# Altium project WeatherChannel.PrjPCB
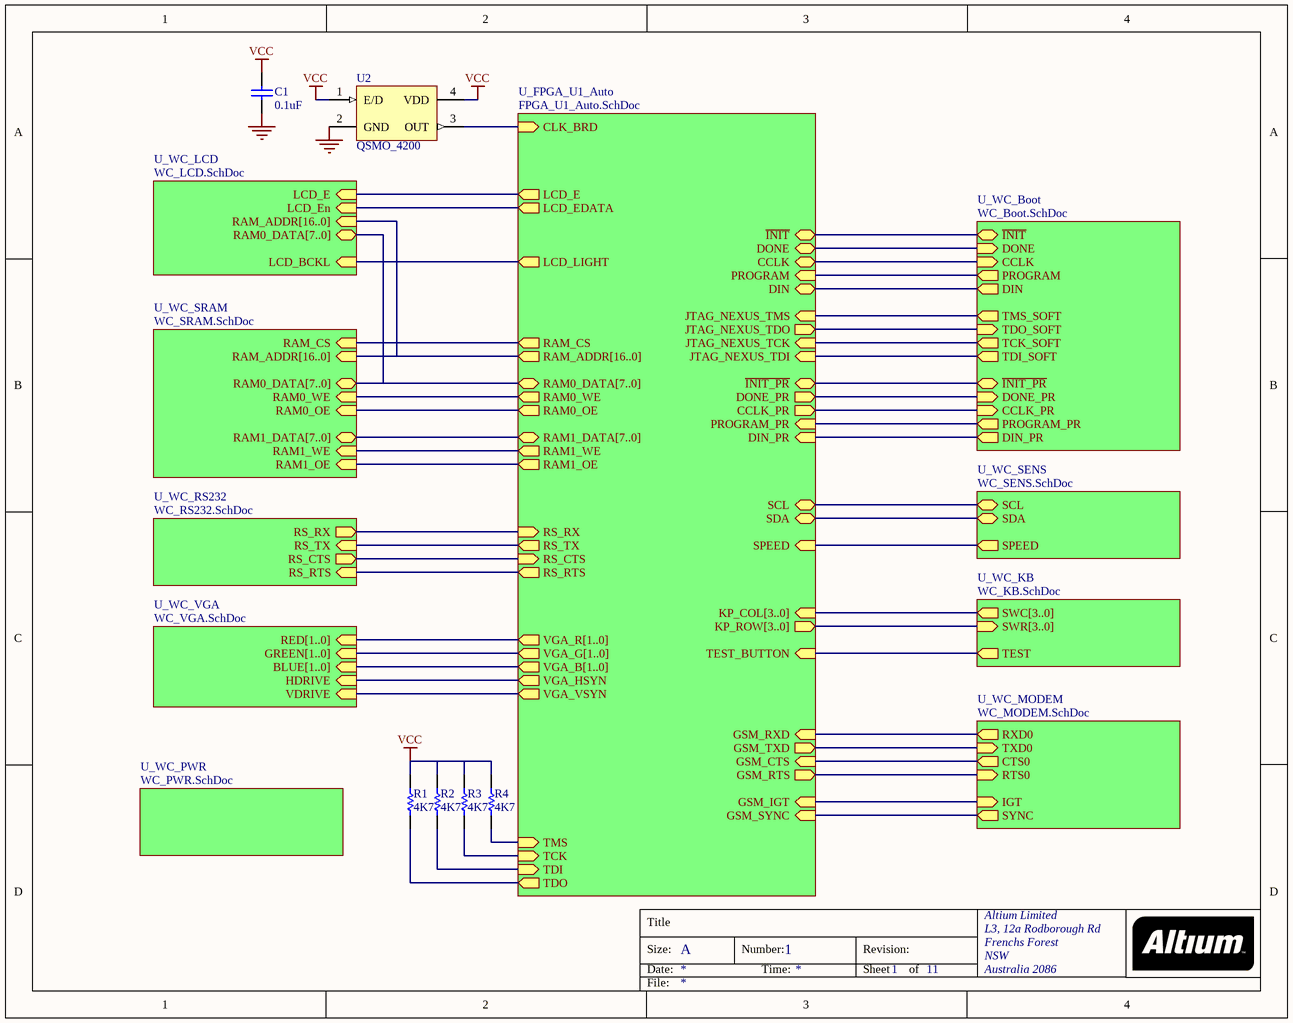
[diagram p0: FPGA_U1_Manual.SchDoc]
11 sheets, 128 parts. Net scope: hierarchical (ports join the sheet entries above them; power ports are global).
Board file: WeatherChannel.PcbDoc
Sheets:
  FPGA_U1_Manual.SchDoc
    U_FPGA_U1_Auto = FPGA_U1_Auto.SchDoc
    U_WC_SENS = WC_SENS.SchDoc
    U_WC_LCD = WC_LCD.SchDoc
    U_WC_SRAM = WC_SRAM.SchDoc
    U_WC_VGA = WC_VGA.SchDoc
    U_WC_RS232 = WC_RS232.SchDoc
    U_WC_KB = WC_KB.SchDoc
    U_WC_PWR = WC_PWR.SchDoc
    U_WC_Boot = WC_Boot.SchDoc
    U_WC_MODEM = WC_MODEM.SchDoc

## Sheet FPGA_U1_Manual.SchDoc
size A; Organization: Altium Limited; Address1: L3, 12a Rodborough Rd; Address2: Frenchs Forest; Address3: NSW; Address4: Australia 2086; DocumentNumber: 1; SheetNumber: 1; SheetTotal: 11

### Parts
C1  0.1uF  [CC2012-0805]
R1  4K7  [CC2012-0805]
R2  4K7  [CC2012-0805]
R3  4K7  [CC2012-0805]
R4  4K7  [CC2012-0805]
U2  QSMO_4200  [QSMO_4200]

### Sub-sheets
U_FPGA_U1_Auto = FPGA_U1_Auto.SchDoc: CLK_BRD (in), SPEED (in), JTAG_NEXUS_TCK (in), JTAG_NEXUS_TDI (in), JTAG_NEXUS_TDO (out), JTAG_NEXUS_TMS (in), KP_COL[3..0] (in), KP_ROW[3..0] (out), LCD_E (out), LCD_EDATA (out), LCD_LIGHT (out), RAM_ADDR[16..0] (out), RAM_CS (out), RAM0_DATA[7..0] (bidir), RAM0_OE (out), RAM0_WE (out), RAM1_DATA[7..0] (bidir), RAM1_OE (out), RAM1_WE (out), RS_CTS (in), RS_RTS (out), RS_RX (in), RS_TX (out), SCL (bidir), SDA (bidir), TEST_BUTTON (in), VGA_B[1..0] (out), VGA_G[1..0] (out), VGA_HSYN (out), VGA_R[1..0] (out), VGA_VSYN (out), CCLK (bidir), DONE (bidir), PROGRAM (in), TCK (in), TDI (in), TDO (out), TMS (in), GSM_CTS (in), GSM_IGT (in), GSM_RTS (out), GSM_RXD (in), GSM_SYNC (in), GSM_TXD (out), CCLK_PR (out), DIN_PR (in), DONE_PR (out), PROGRAM_PR (in), ~{INIT_PR} (bidir), ~{INIT} (bidir), DIN (bidir)
U_WC_Boot = WC_Boot.SchDoc: ~{INIT} (bidir), DONE (in), CCLK (in), ~{INIT_PR} (bidir), DONE_PR (in), CCLK_PR (in), DIN (out), DIN_PR (out), PROGRAM (out), PROGRAM_PR (out), TMS_SOFT (out), TDO_SOFT (in), TCK_SOFT (out), TDI_SOFT (out)
U_WC_KB = WC_KB.SchDoc: TEST (out), SWR[3..0] (in), SWC[3..0] (out)
U_WC_LCD = WC_LCD.SchDoc: LCD_E (in), LCD_BCKL (in), LCD_En (in), RAM0_DATA[7..0] (bidir), RAM_ADDR[16..0] (in)
U_WC_MODEM = WC_MODEM.SchDoc: TXD0 (in), RXD0 (out), IGT (in), RTS0 (in), CTS0 (out), SYNC (out)
U_WC_PWR = WC_PWR.SchDoc: no entries
U_WC_RS232 = WC_RS232.SchDoc: RS_RTS (in), RS_TX (in), RS_CTS (out), RS_RX (out)
U_WC_SENS = WC_SENS.SchDoc: SCL (bidir), SDA (bidir), SPEED (out)
U_WC_SRAM = WC_SRAM.SchDoc: RAM0_WE (in), RAM0_OE (in), RAM1_WE (in), RAM1_OE (in), RAM_CS (in), RAM0_DATA[7..0] (bidir), RAM1_DATA[7..0] (bidir), RAM_ADDR[16..0] (in)
U_WC_VGA = WC_VGA.SchDoc: RED[1..0] (in), GREEN[1..0] (in), BLUE[1..0] (in), HDRIVE (in), VDRIVE (in)

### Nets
GND: C1.2 U2.2(GND)
VCC: C1.1 R1.1 R2.1 R3.1 R4.1 U2.1(E/D) U2.4(VDD)
CCLK: sheet U_FPGA_U1_Auto/CCLK, sheet U_WC_Boot/CCLK
CCLK_PR: sheet U_FPGA_U1_Auto/CCLK_PR, sheet U_WC_Boot/CCLK_PR
CLK_BRD: U2.3(OUT) ; sheet U_FPGA_U1_Auto/CLK_BRD
DIN: sheet U_FPGA_U1_Auto/DIN, sheet U_WC_Boot/DIN
DIN_PR: sheet U_FPGA_U1_Auto/DIN_PR, sheet U_WC_Boot/DIN_PR
DONE: sheet U_FPGA_U1_Auto/DONE, sheet U_WC_Boot/DONE
DONE_PR: sheet U_FPGA_U1_Auto/DONE_PR, sheet U_WC_Boot/DONE_PR
GSM_CTS: sheet U_FPGA_U1_Auto/GSM_CTS, sheet U_WC_MODEM/CTS0
GSM_IGT: sheet U_FPGA_U1_Auto/GSM_IGT, sheet U_WC_MODEM/IGT
GSM_RTS: sheet U_FPGA_U1_Auto/GSM_RTS, sheet U_WC_MODEM/RTS0
GSM_RXD: sheet U_FPGA_U1_Auto/GSM_RXD, sheet U_WC_MODEM/RXD0
GSM_SYNC: sheet U_FPGA_U1_Auto/GSM_SYNC, sheet U_WC_MODEM/SYNC
GSM_TXD: sheet U_FPGA_U1_Auto/GSM_TXD, sheet U_WC_MODEM/TXD0
~{INIT}: sheet U_FPGA_U1_Auto/~{INIT}, sheet U_WC_Boot/~{INIT}
~{INIT_PR}: sheet U_FPGA_U1_Auto/~{INIT_PR}, sheet U_WC_Boot/~{INIT_PR}
JTAG_NEXUS_TCK: sheet U_FPGA_U1_Auto/JTAG_NEXUS_TCK, sheet U_WC_Boot/TCK_SOFT
JTAG_NEXUS_TDI: sheet U_FPGA_U1_Auto/JTAG_NEXUS_TDI, sheet U_WC_Boot/TDI_SOFT
JTAG_NEXUS_TDO: sheet U_FPGA_U1_Auto/JTAG_NEXUS_TDO, sheet U_WC_Boot/TDO_SOFT
JTAG_NEXUS_TMS: sheet U_FPGA_U1_Auto/JTAG_NEXUS_TMS, sheet U_WC_Boot/TMS_SOFT
LCD_BCKL: sheet U_FPGA_U1_Auto/LCD_LIGHT, sheet U_WC_LCD/LCD_BCKL
LCD_E: sheet U_FPGA_U1_Auto/LCD_E, sheet U_WC_LCD/LCD_E
LCD_EDATA: sheet U_FPGA_U1_Auto/LCD_EDATA, sheet U_WC_LCD/LCD_En
PROGRAM: sheet U_FPGA_U1_Auto/PROGRAM, sheet U_WC_Boot/PROGRAM
PROGRAM_PR: sheet U_FPGA_U1_Auto/PROGRAM_PR, sheet U_WC_Boot/PROGRAM_PR
RAM0_OE: sheet U_FPGA_U1_Auto/RAM0_OE, sheet U_WC_SRAM/RAM0_OE
RAM0_WE: sheet U_FPGA_U1_Auto/RAM0_WE, sheet U_WC_SRAM/RAM0_WE
RAM1_OE: sheet U_FPGA_U1_Auto/RAM1_OE, sheet U_WC_SRAM/RAM1_OE
RAM1_WE: sheet U_FPGA_U1_Auto/RAM1_WE, sheet U_WC_SRAM/RAM1_WE
RAM_CS: sheet U_FPGA_U1_Auto/RAM_CS, sheet U_WC_SRAM/RAM_CS
RS_CTS: sheet U_FPGA_U1_Auto/RS_CTS, sheet U_WC_RS232/RS_CTS
RS_RTS: sheet U_FPGA_U1_Auto/RS_RTS, sheet U_WC_RS232/RS_RTS
RS_RX: sheet U_FPGA_U1_Auto/RS_RX, sheet U_WC_RS232/RS_RX
RS_TX: sheet U_FPGA_U1_Auto/RS_TX, sheet U_WC_RS232/RS_TX
SCL: sheet U_FPGA_U1_Auto/SCL, sheet U_WC_SENS/SCL
SDA: sheet U_FPGA_U1_Auto/SDA, sheet U_WC_SENS/SDA
SPEED: sheet U_FPGA_U1_Auto/SPEED, sheet U_WC_SENS/SPEED
TCK: R3.2 ; sheet U_FPGA_U1_Auto/TCK
TDI: R2.2 ; sheet U_FPGA_U1_Auto/TDI
TDO: R1.2 ; sheet U_FPGA_U1_Auto/TDO
TEST: sheet U_FPGA_U1_Auto/TEST_BUTTON, sheet U_WC_KB/TEST
TMS: R4.2 ; sheet U_FPGA_U1_Auto/TMS
VGA_HSYN: sheet U_FPGA_U1_Auto/VGA_HSYN, sheet U_WC_VGA/HDRIVE
VGA_VSYN: sheet U_FPGA_U1_Auto/VGA_VSYN, sheet U_WC_VGA/VDRIVE

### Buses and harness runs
bus sheet U_FPGA_U1_Auto/KP_COL[3..0] = sheet U_WC_KB/SWC[3..0]
bus sheet U_FPGA_U1_Auto/KP_ROW[3..0] = sheet U_WC_KB/SWR[3..0]
bus sheet U_FPGA_U1_Auto/RAM0_DATA[7..0] = sheet U_WC_LCD/RAM0_DATA[7..0] = sheet U_WC_SRAM/RAM0_DATA[7..0]
bus sheet U_FPGA_U1_Auto/RAM1_DATA[7..0] = sheet U_WC_SRAM/RAM1_DATA[7..0]
bus sheet U_FPGA_U1_Auto/RAM_ADDR[16..0] = sheet U_WC_LCD/RAM_ADDR[16..0] = sheet U_WC_SRAM/RAM_ADDR[16..0]
bus sheet U_FPGA_U1_Auto/VGA_B[1..0] = sheet U_WC_VGA/BLUE[1..0]
bus sheet U_FPGA_U1_Auto/VGA_G[1..0] = sheet U_WC_VGA/GREEN[1..0]
bus sheet U_FPGA_U1_Auto/VGA_R[1..0] = sheet U_WC_VGA/RED[1..0]

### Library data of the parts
C1 = CAP: Capacitor
R1-R4 = RES: Resistor
U2 = QSMO_4200: Surface Mount Crystal Oscillator

## Sheet FPGA_U1_Auto.SchDoc
size A2; Generated From FPGA Project: WeatherChannel.PrjFpg; UNUSED_SPECIAL: RouteSeparate; UNUSED_IO: NoERC; VREF: NoERC; UNUSED_INPUT: NoERC; DocumentNumber: 11; SheetNumber: 11; SheetTotal: 11
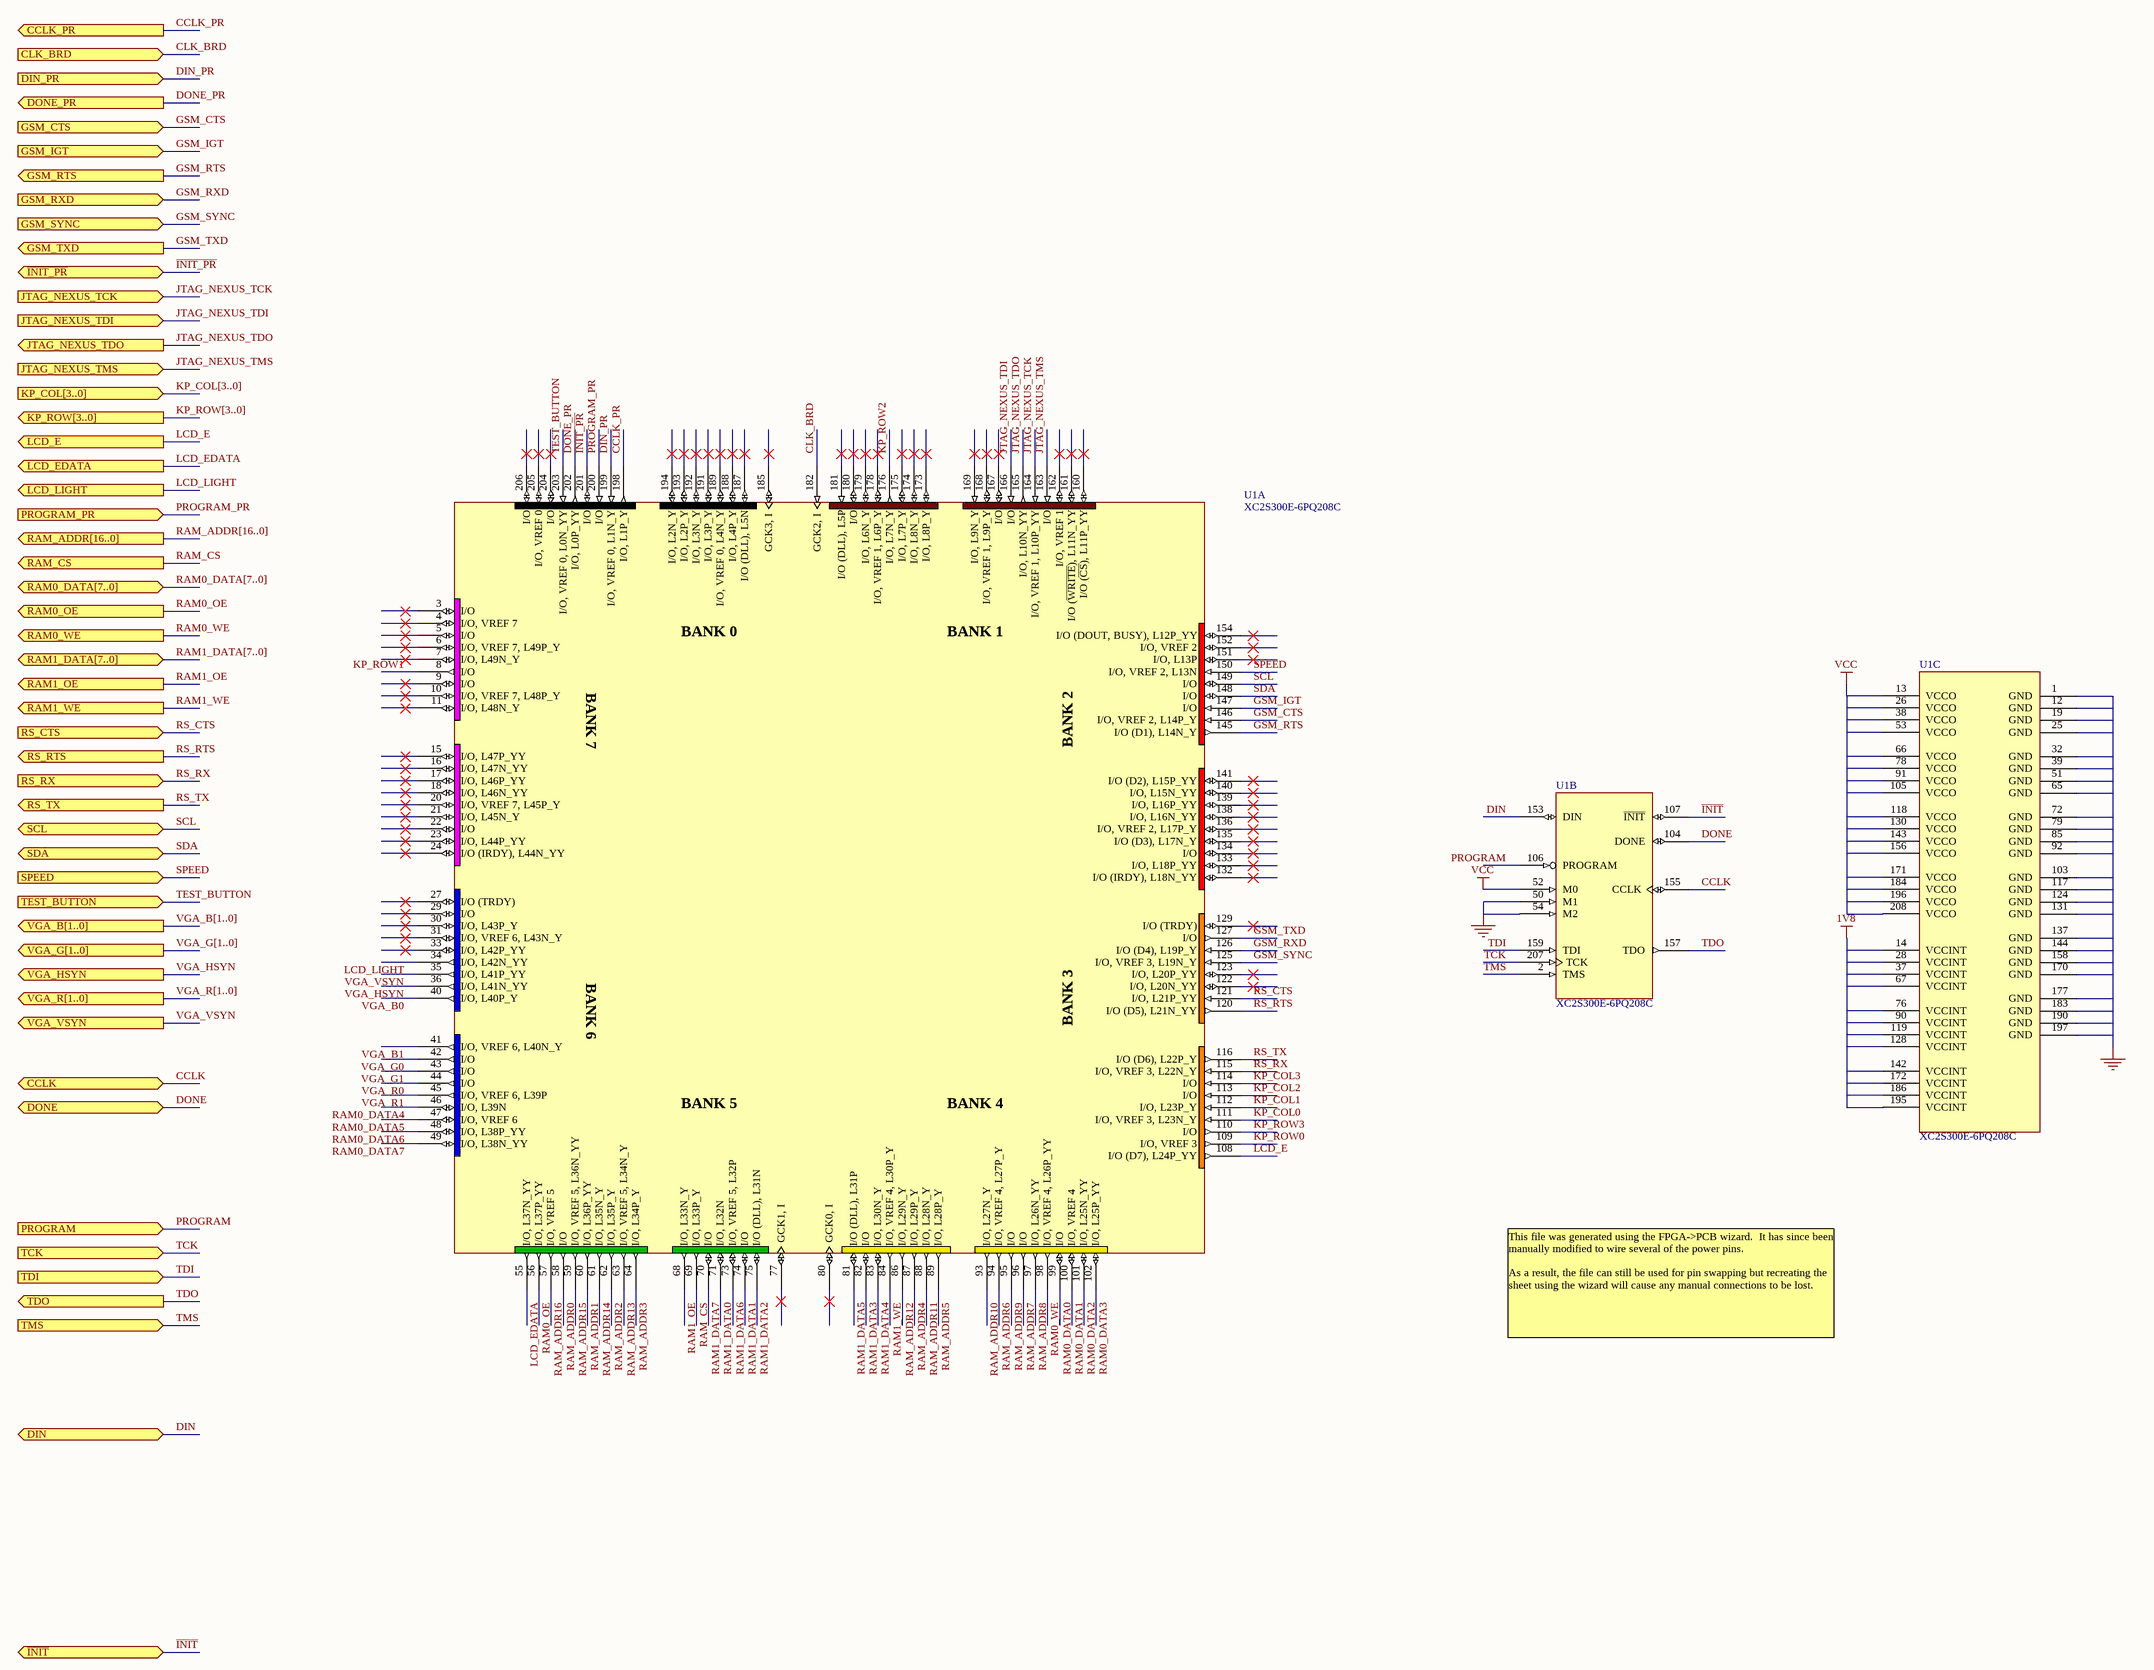
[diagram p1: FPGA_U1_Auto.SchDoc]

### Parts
U1  XC2S300E-6PQ208C  [PQ208]  (parts A,B,C of 3)

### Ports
CCLK (bidir), CCLK_PR (out), CLK_BRD (in), DIN (bidir), DIN_PR (in), DONE (bidir), DONE_PR (out), GSM_CTS (in), GSM_IGT (in), GSM_RTS (out), GSM_RXD (in), GSM_SYNC (in), GSM_TXD (out), JTAG_NEXUS_TCK (in), JTAG_NEXUS_TDI (in), JTAG_NEXUS_TDO (out), JTAG_NEXUS_TMS (in), KP_COL[3..0] (in), KP_ROW[3..0] (out), LCD_E (out), LCD_EDATA (out), LCD_LIGHT (out), PROGRAM (in), PROGRAM_PR (in), RAM0_DATA[7..0] (bidir), RAM0_OE (out), RAM0_WE (out), RAM1_DATA[7..0] (bidir), RAM1_OE (out), RAM1_WE (out), RAM_ADDR[16..0] (out), RAM_CS (out), RS_CTS (in), RS_RTS (out), RS_RX (in), RS_TX (out), SCL (bidir), SDA (bidir), SPEED (in), TCK (in), TDI (in), TDO (out), TEST_BUTTON (in), TMS (in), VGA_B[1..0] (out), VGA_G[1..0] (out), VGA_HSYN (out), VGA_R[1..0] (out), VGA_VSYN (out), ~{INIT_PR} (bidir), ~{INIT} (bidir)

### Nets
1V8: U1.14(VCCINT) U1.28(VCCINT) U1.37(VCCINT) U1.67(VCCINT) U1.76(VCCINT) U1.90(VCCINT) U1.119(VCCINT) U1.128(VCCINT) U1.142(VCCINT) U1.172(VCCINT) U1.186(VCCINT) U1.195(VCCINT)
GND: U1.1(GND) U1.12(GND) U1.19(GND) U1.25(GND) U1.32(GND) U1.39(GND) U1.50(M1) U1.51(GND) U1.54(M2) U1.65(GND) U1.72(GND) U1.79(GND) U1.85(GND) U1.92(GND) U1.103(GND) U1.117(GND) U1.124(GND) U1.131(GND) U1.137(GND) U1.144(GND) U1.158(GND) U1.170(GND) U1.177(GND) U1.183(GND) U1.190(GND) U1.197(GND)
VCC: U1.13(VCCO) U1.26(VCCO) U1.38(VCCO) U1.52(M0) U1.53(VCCO) U1.66(VCCO) U1.78(VCCO) U1.91(VCCO) U1.105(VCCO) U1.118(VCCO) U1.130(VCCO) U1.143(VCCO) U1.156(VCCO) U1.171(VCCO) U1.184(VCCO) U1.196(VCCO) U1.208(VCCO)
CCLK: U1.155(CCLK) ; port CCLK
CCLK_PR: U1.198(I/O,_L1P_Y) ; port CCLK_PR
CLK_BRD: U1.182(GCK2,_I) ; port CLK_BRD
DIN: U1.153(DIN) ; port DIN
DIN_PR: U1.199(I/O,_VREF_0,_L1N_Y) ; port DIN_PR
DONE: U1.104(DONE) ; port DONE
DONE_PR: U1.202(I/O,_L0P_YY) ; port DONE_PR
GSM_CTS: U1.146(I/O,_VREF_2,_L14P_Y) ; port GSM_CTS
GSM_IGT: U1.147(I/O) ; port GSM_IGT
GSM_RTS: U1.145(I/O_(D1),_L14N_Y) ; port GSM_RTS
GSM_RXD: U1.126(I/O_(D4),_L19P_Y) ; port GSM_RXD
GSM_SYNC: U1.125(I/O,_VREF_3,_L19N_Y) ; port GSM_SYNC
GSM_TXD: U1.127(I/O) ; port GSM_TXD
~{INIT}: U1.107(~{INIT}) ; port ~{INIT}
~{INIT_PR}: U1.201(I/O) ; port ~{INIT_PR}
JTAG_NEXUS_TCK: U1.164(I/O,_VREF_1,_L10P_YY) ; port JTAG_NEXUS_TCK
JTAG_NEXUS_TDI: U1.166(I/O) ; port JTAG_NEXUS_TDI
JTAG_NEXUS_TDO: U1.165(I/O,_L10N_YY) ; port JTAG_NEXUS_TDO
JTAG_NEXUS_TMS: U1.163(I/O) ; port JTAG_NEXUS_TMS
KP_COL0: U1.111(I/O,_VREF_3,_L23N_Y)
KP_COL1: U1.112(I/O,_L23P_Y)
KP_COL2: U1.113(I/O)
KP_COL3: U1.114(I/O)
KP_ROW0: U1.109(I/O,_VREF_3)
KP_ROW1: U1.8(I/O)
KP_ROW2: U1.176(I/O,_L7N_Y)
KP_ROW3: U1.110(I/O)
LCD_E: U1.108(I/O_(D7),_L24P_YY) ; port LCD_E
LCD_EDATA: U1.55(I/O,_L37N_YY) ; port LCD_EDATA
LCD_LIGHT: U1.34(I/O,_L42N_YY) ; port LCD_LIGHT  [project net LCD_BCKL]
PROGRAM: U1.106(PROGRAM) ; port PROGRAM
PROGRAM_PR: U1.200(I/O) ; port PROGRAM_PR
RAM0_DATA0: U1.99(I/O)
RAM0_DATA1: U1.100(I/O,_VREF_4)
RAM0_DATA2: U1.101(I/O,_L25N_YY)
RAM0_DATA3: U1.102(I/O,_L25P_YY)
RAM0_DATA4: U1.46(I/O,_L39N)
RAM0_DATA5: U1.47(I/O,_VREF_6)
RAM0_DATA6: U1.48(I/O,_L38P_YY)
RAM0_DATA7: U1.49(I/O,_L38N_YY)
RAM0_OE: U1.56(I/O,_L37P_YY) ; port RAM0_OE
RAM0_WE: U1.98(I/O,_VREF_4,_L26P_YY) ; port RAM0_WE
RAM1_DATA0: U1.71(I/O,_L32N)
RAM1_DATA1: U1.74(I/O)
RAM1_DATA2: U1.75(I/O_(DLL),_L31N)
RAM1_DATA3: U1.82(I/O)
RAM1_DATA4: U1.83(I/O,_L30N_Y)
RAM1_DATA5: U1.81(I/O_(DLL),_L31P)
RAM1_DATA6: U1.73(I/O,_VREF_5,_L32P)
RAM1_DATA7: U1.70(I/O)
RAM1_OE: U1.68(I/O,_L33N_Y) ; port RAM1_OE
RAM1_WE: U1.84(I/O,_VREF_4,_L30P_Y) ; port RAM1_WE
RAM_ADDR0: U1.58(I/O)
RAM_ADDR1: U1.60(I/O,_L36P_YY)
RAM_ADDR2: U1.62(I/O,_L35P_Y)
RAM_ADDR3: U1.64(I/O,_L34P_Y)
RAM_ADDR4: U1.87(I/O,_L29P_Y)
RAM_ADDR5: U1.89(I/O,_L28P_Y)
RAM_ADDR6: U1.94(I/O,_VREF_4,_L27P_Y)
RAM_ADDR7: U1.96(I/O)
RAM_ADDR8: U1.97(I/O,_L26N_YY)
RAM_ADDR9: U1.95(I/O)
RAM_ADDR10: U1.93(I/O,_L27N_Y)
RAM_ADDR11: U1.88(I/O,_L28N_Y)
RAM_ADDR12: U1.86(I/O,_L29N_Y)
RAM_ADDR13: U1.63(I/O,_VREF_5,_L34N_Y)
RAM_ADDR14: U1.61(I/O,_L35N_Y)
RAM_ADDR15: U1.59(I/O,_VREF_5,_L36N_YY)
RAM_ADDR16: U1.57(I/O,_VREF_5)
RAM_CS: U1.69(I/O,_L33P_Y) ; port RAM_CS
RS_CTS: U1.121(I/O,_L21P_YY) ; port RS_CTS
RS_RTS: U1.120(I/O_(D5),_L21N_YY) ; port RS_RTS
RS_RX: U1.115(I/O,_VREF_3,_L22N_Y) ; port RS_RX
RS_TX: U1.116(I/O_(D6),_L22P_Y) ; port RS_TX
SCL: U1.149(I/O) ; port SCL
SDA: U1.148(I/O) ; port SDA
SPEED: U1.150(I/O,_VREF_2,_L13N) ; port SPEED
TCK: U1.207(TCK) ; port TCK
TDI: U1.159(TDI) ; port TDI
TDO: U1.157(TDO) ; port TDO
TEST_BUTTON: U1.203(I/O,_VREF_0,_L0N_YY) ; port TEST_BUTTON  [project net TEST]
TMS: U1.2(TMS) ; port TMS
VGA_B0: U1.40(I/O,_L40P_Y)  [project net BLUE0]
VGA_B1: U1.41(I/O,_VREF_6,_L40N_Y)  [project net BLUE1]
VGA_G0: U1.42(I/O)  [project net GREEN0]
VGA_G1: U1.43(I/O)  [project net GREEN1]
VGA_HSYN: U1.36(I/O,_L41N_YY) ; port VGA_HSYN
VGA_R0: U1.44(I/O)  [project net RED0]
VGA_R1: U1.45(I/O,_VREF_6,_L39P)  [project net RED1]
VGA_VSYN: U1.35(I/O,_L41P_YY) ; port VGA_VSYN

Not connected (* = marked no-connect by the designer): U1 3(I/O)* 4(I/O,_VREF_7)* 5(I/O)* 6(I/O,_VREF_7,_L49P_Y)* 7(I/O,_L49N_Y)* 9(I/O)* 10(I/O,_VREF_7,_L48P_Y)* 11(I/O,_L48N_Y)* 15(I/O,_L47P_YY)* 16(I/O,_L47N_YY)* 17(I/O,_L46P_YY)* 18(I/O,_L46N_YY)* 20(I/O,_VREF_7,_L45P_Y)* 21(I/O,_L45N_Y)* 22(I/O)* 23(I/O,_L44P_YY)* 24(I/O_(IRDY),_L44N_YY)* 27(I/O_(TRDY))* 29(I/O)* 30(I/O,_L43P_Y)* 31(I/O,_VREF_6,_L43N_Y)* 33(I/O,_L42P_YY)* 77(GCK1,_I)* 80(GCK0,_I)* 122(I/O,_L20N_YY)* 123(I/O,_L20P_YY)* 129(I/O_(TRDY))* 132(I/O_(IRDY),_L18N_YY)* 133(I/O,_L18P_YY)* 134(I/O)* 135(I/O_(D3),_L17N_Y)* 136(I/O,_VREF_2,_L17P_Y)* 138(I/O,_L16N_YY)* 139(I/O,_L16P_YY)* 140(I/O,_L15N_YY)* 141(I/O_(D2),_L15P_YY)* 151(I/O,_L13P)* 152(I/O,_VREF_2)* 154(I/O_(DOUT,_BUSY),_L12P_YY)* 160(I/O_(~{CS}),_L11P_YY)* 161(I/O_(~{WRITE}),_L11N_YY)* 162(I/O,_VREF_1)* 167(I/O)* 168(I/O,_VREF_1,_L9P_Y)* 169(I/O,_L9N_Y)* 173(I/O,_L8P_Y)* 174(I/O,_L8N_Y)* 175(I/O,_L7P_Y)* 178(I/O,_VREF_1,_L6P_Y)* 179(I/O,_L6N_Y)* 180(I/O)* 181(I/O_(DLL),_L5P)* 185(GCK3,_I)* 187(I/O_(DLL),_L5N)* 188(I/O,_L4P_Y)* 189(I/O,_VREF_0,_L4N_Y)* 191(I/O,_L3P_Y)* 192(I/O,_L3N_Y)* 193(I/O,_L2P_Y)* 194(I/O,_L2N_Y)* 204(I/O)* 205(I/O,_VREF_0)* 206(I/O)*

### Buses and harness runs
bus KP_COL[3..0] = port KP_COL[3..0]
bus KP_ROW[3..0] = port KP_ROW[3..0]
bus RAM0_DATA[7..0] = port RAM0_DATA[7..0]
bus RAM1_DATA[7..0] = port RAM1_DATA[7..0]
bus RAM_ADDR[16..0] = port RAM_ADDR[16..0]
bus VGA_B[1..0] = port VGA_B[1..0]
bus VGA_G[1..0] = port VGA_G[1..0]
bus VGA_R[1..0] = port VGA_R[1..0]

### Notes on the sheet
- This file was generated using the FPGA->PCB wizard.  It has since been manually modified to wire several of the power pins.
  As a result, the file can still be used for pin swapping but recreating the sheet using the wizard will cause any manual connections to be lost.

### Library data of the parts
U1 = XC2S300E-6PQ208C: Spartan-IIE 1.8V FPGA, 208-Pin PQFP, Standard Performance, Commercial Grade; Package Information: Latest Revision: ver1.1, Oct-2002; Code - JEDEC: MS-029-FA-1

## Sheet WC_SENS.SchDoc
size A; Organization: Altium Limited; Address1: L3, 12a Rodborough Rd; Address2: Frenchs Forest; Address3: NSW; Address4: Australia 2086; DocumentNumber: 10; SheetNumber: 10; SheetTotal: 11
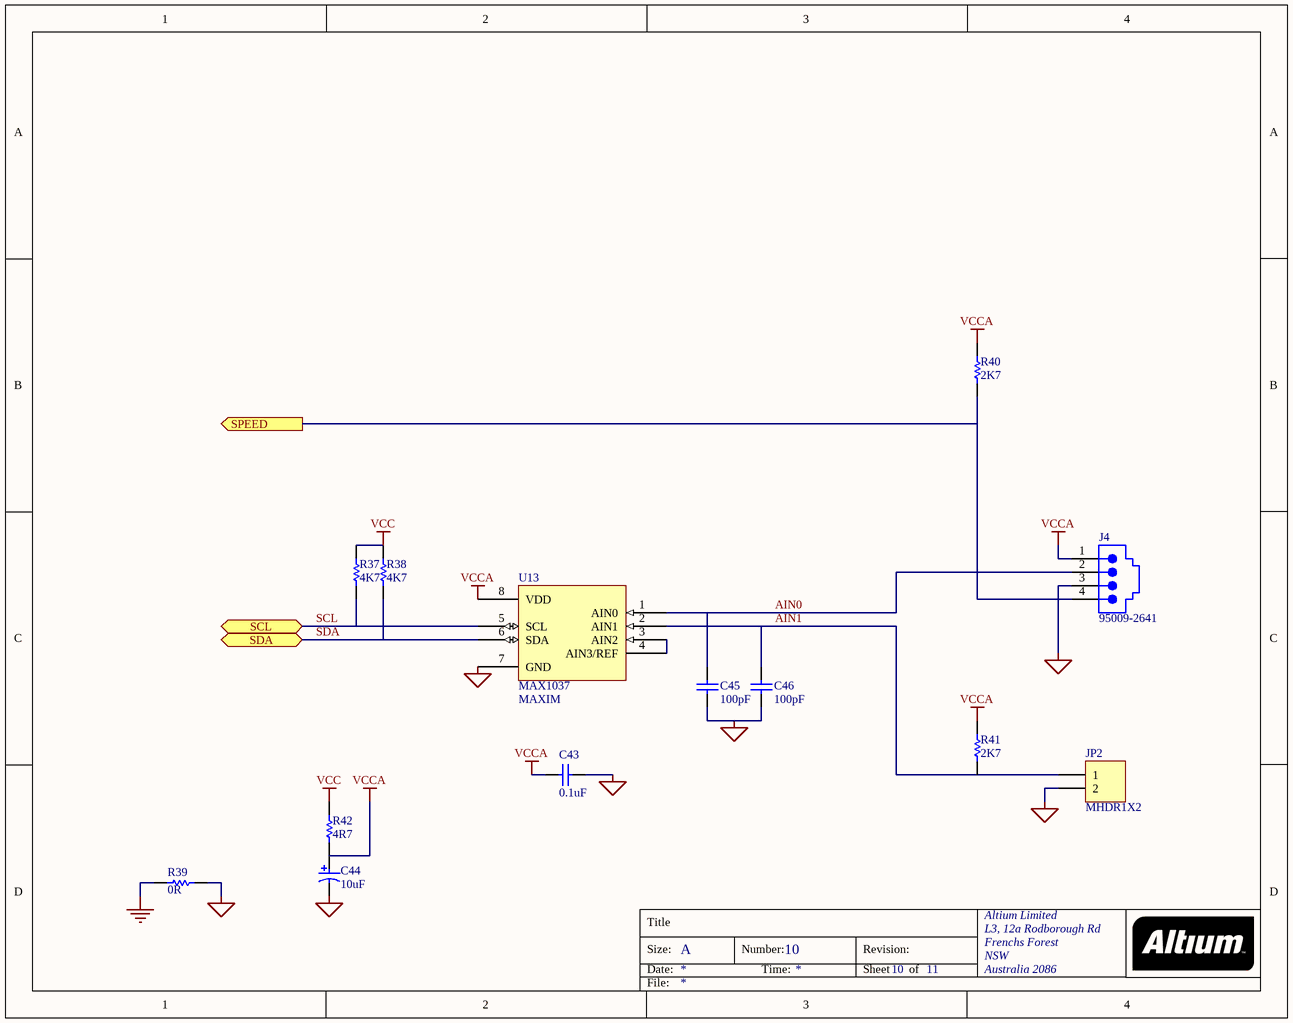
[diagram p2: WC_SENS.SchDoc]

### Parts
C43  0.1uF  [CC2012-0805]
C44  10uF  [MCCT-B]
C45  100pF  [CC2012-0805]
C46  100pF  [CC2012-0805]
J4  95009-2641  [JACK1.27-2H4D]
JP2  MHDR1X2  [TS2.54x2]
R37  4K7  [CC2012-0805]
R38  4K7  [CC2012-0805]
R39  0R  [CC2012-0805]
R40  2K7  [CC2012-0805]
R41  2K7  [CC2012-0805]
R42  4R7  [CC2012-0805]
U13  MAX1037  Supplier: MAXIM  [SOT23_8]

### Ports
SCL (bidir), SDA (bidir), SPEED (out)

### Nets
AGND: C43.2 C44.2 C45.2 C46.2 J4.3 JP2.2 R39.2 U13.7(GND)
GND: R39.1
VCC: R37.1 R38.1 R42.1
VCCA: C43.1 C44.1 J4.1 R40.1 R41.1 R42.2 U13.8(VDD)
AIN0: C45.1 J4.2 U13.1(AIN0)
AIN1: C46.1 JP2.1 R41.2 U13.2(AIN1)
SCL: R37.2 U13.5(SCL) ; port SCL
SDA: R38.2 U13.6(SDA) ; port SDA
SPEED: J4.4 R40.2 ; port SPEED
NetU13_3: U13.3(AIN2) U13.4(AIN3/REF)

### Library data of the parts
C43 C45 C46 = CAP: Capacitor
C44 = CAP_POLAR: Polar Capacitor
J4 = 95009-2641: Right Angle, Standard Profile, with Mounting Rib, Flush Mount PCB Jack; Manufacturer: Molex; Package Information: Latest Revision: Dec-2001; Ports: 1; Positions/Loaded: Port1; PCB Mounting: Thru-Hole; Drill Diameter: Nominal, Rounded to nearest 0.05mm; PCB Layout: Complies with Manufacturer's Recommendation.
JP2 = MHDR1X2: Header, 2-Pin; Manufacturer: Generic Components; Class I: Connector
R37-R42 = RES: Resistor
U13 = MAX1037: 4 Channel 8 Bit ADC, I2C interface, 2.7V to 3.6V Supply

## Sheet WC_LCD.SchDoc
size A; Organization: Altium Limited; Address1: L3, 12a Rodborough Rd; Address2: Frenchs Forest; Address3: NSW; Address4: Australia 2086; DocumentNumber: 2; SheetNumber: 2; SheetTotal: 11
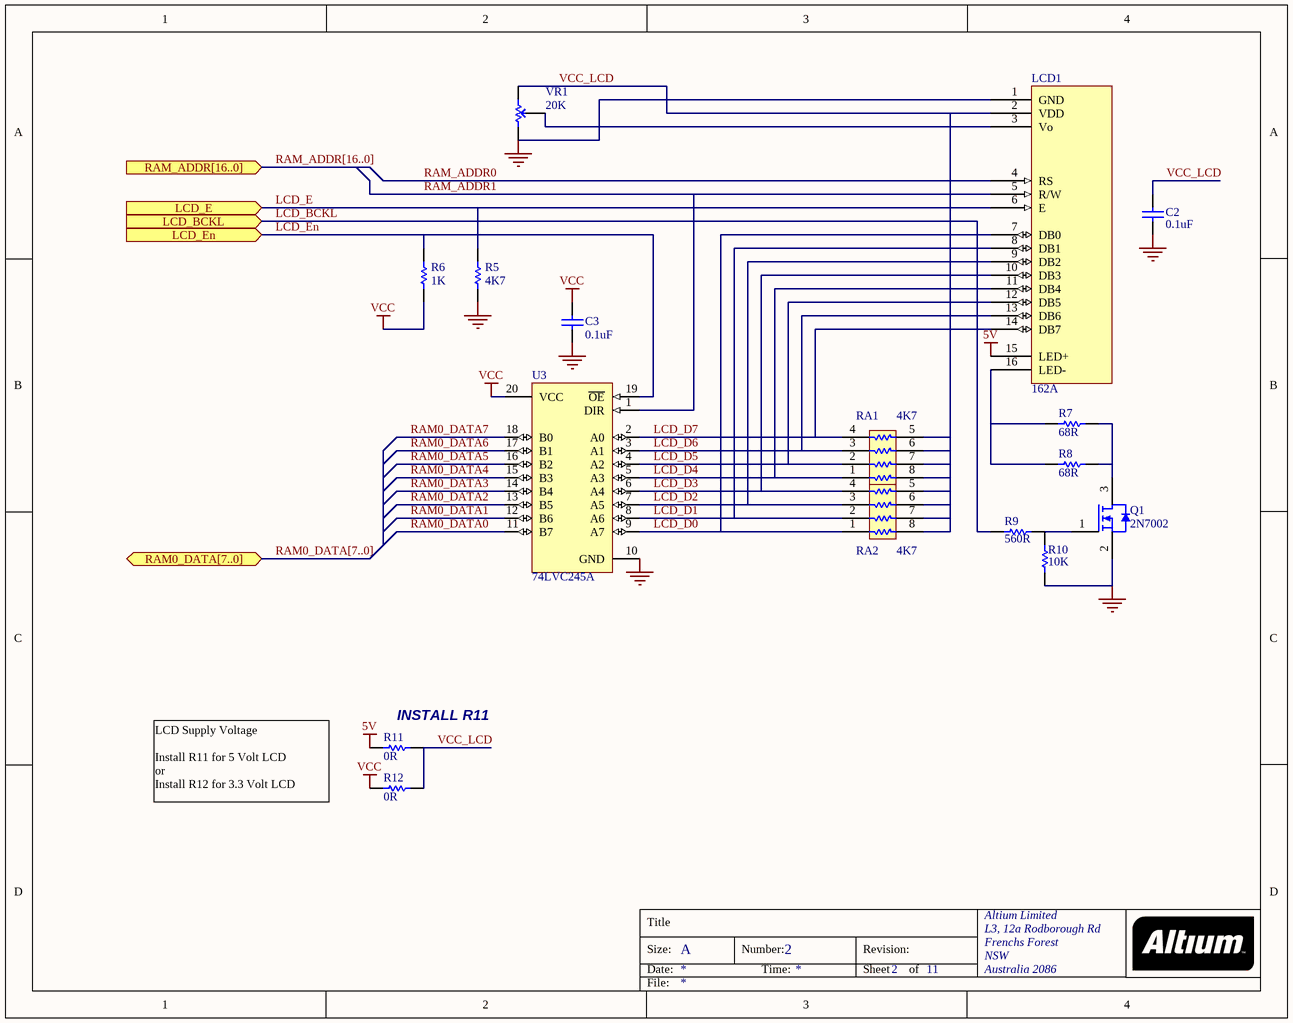
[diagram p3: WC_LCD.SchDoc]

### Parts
C2  0.1uF  [CC2012-0805]
C3  0.1uF  [CC2012-0805]
LCD1  162A  [162A]
Q1  2N7002  [SO-G3]
R5  4K7  [CC2012-0805]
R6  1K  [CC2012-0805]
R7  68R  [CC2012-0805]
R8  68R  [CC2012-0805]
R9  560R  [CC2012-0805]
R10  10K  [CC2012-0805]
R11  0R  [CC2012-0805]
R12  0R  [CC2012-0805]
RA1  4K7  [MNR34]
RA2  4K7  [MNR34]
U3  74LVC245A  [SSO-G20/P.65]
VR1  20K  [POT4MM-2]

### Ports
LCD_BCKL (in), LCD_E (in), LCD_En (in), RAM0_DATA[7..0] (bidir), RAM_ADDR[16..0] (in)

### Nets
5V: LCD1.15(LED+) R11.1
GND: C2.2 C3.2 LCD1.1(GND) Q1.2 R5.2 R10.1 U3.10(GND) VR1.CCW(-)
VCC: C3.1 R6.2 R12.1 U3.20(VCC)
LCD_BCKL: R9.1 ; port LCD_BCKL
LCD_D0: LCD1.7(DB0) RA2.1 U3.9(A7)
LCD_D1: LCD1.8(DB1) RA2.2 U3.8(A6)
LCD_D2: LCD1.9(DB2) RA2.3 U3.7(A5)
LCD_D3: LCD1.10(DB3) RA2.4 U3.6(A4)
LCD_D4: LCD1.11(DB4) RA1.1 U3.5(A3)
LCD_D5: LCD1.12(DB5) RA1.2 U3.4(A2)
LCD_D6: LCD1.13(DB6) RA1.3 U3.3(A1)
LCD_D7: LCD1.14(DB7) RA1.4 U3.2(A0)
LCD_E: LCD1.6(E) R5.1 ; port LCD_E
LCD_En: R6.1 U3.19(~{OE}) ; port LCD_En  [project net LCD_EDATA]
RAM0_DATA0: U3.11(B7)
RAM0_DATA1: U3.12(B6)
RAM0_DATA2: U3.13(B5)
RAM0_DATA3: U3.14(B4)
RAM0_DATA4: U3.15(B3)
RAM0_DATA5: U3.16(B2)
RAM0_DATA6: U3.17(B1)
RAM0_DATA7: U3.18(B0)
RAM_ADDR0: LCD1.4(RS)
RAM_ADDR1: LCD1.5(R/W) U3.1(DIR)
VCC_LCD: C2.1 LCD1.2(VDD) R11.2 R12.2 RA1.5 RA1.6 RA1.7 RA1.8 RA2.5 RA2.6 RA2.7 RA2.8 VR1.CW(+)
NetLCD1_3: LCD1.3(Vo) VR1.W
NetLCD1_16: LCD1.16(LED-) R7.1 R8.1
NetQ1_1: Q1.1 R9.2 R10.2
NetQ1_3: Q1.3 R7.2 R8.2

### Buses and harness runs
bus RAM0_DATA[7..0] = port RAM0_DATA[7..0]
bus RAM_ADDR[16..0] = port RAM_ADDR[16..0]

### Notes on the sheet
- (near R11) INSTALL R11
- LCD Supply Voltage
  Install R11 for 5 Volt LCD
  or
  Install R12 for 3.3 Volt LCD

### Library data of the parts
C2 C3 = CAP: Capacitor
LCD1 = 162A: 16 char * 2 line LCD character display with b/light
Q1 = 2N7002: N Channel Mosfet
R5-R12 = RES: Resistor
RA1 RA2 = MNR34: 3216x4 Resistor Array
U3 = 74LVC245A: Octal Bus Transceiver with 3-State Outputs; Manufacturer: Texas Instruments; Revision 1: 12-July-2000: SIM Model Added.; Revision 2: July-2002: Re-released for DXP Platform.; Class I: Interface; Class II: Line Transceiver
VR1 = POT_M: Potentiometer

## Sheet WC_SRAM.SchDoc
size A; Organization: Altium Limited; Address1: L3, 12a Rodborough Rd; Address2: Frenchs Forest; Address3: NSW; Address4: Australia 2086; DocumentNumber: 5; SheetNumber: 5; SheetTotal: 11
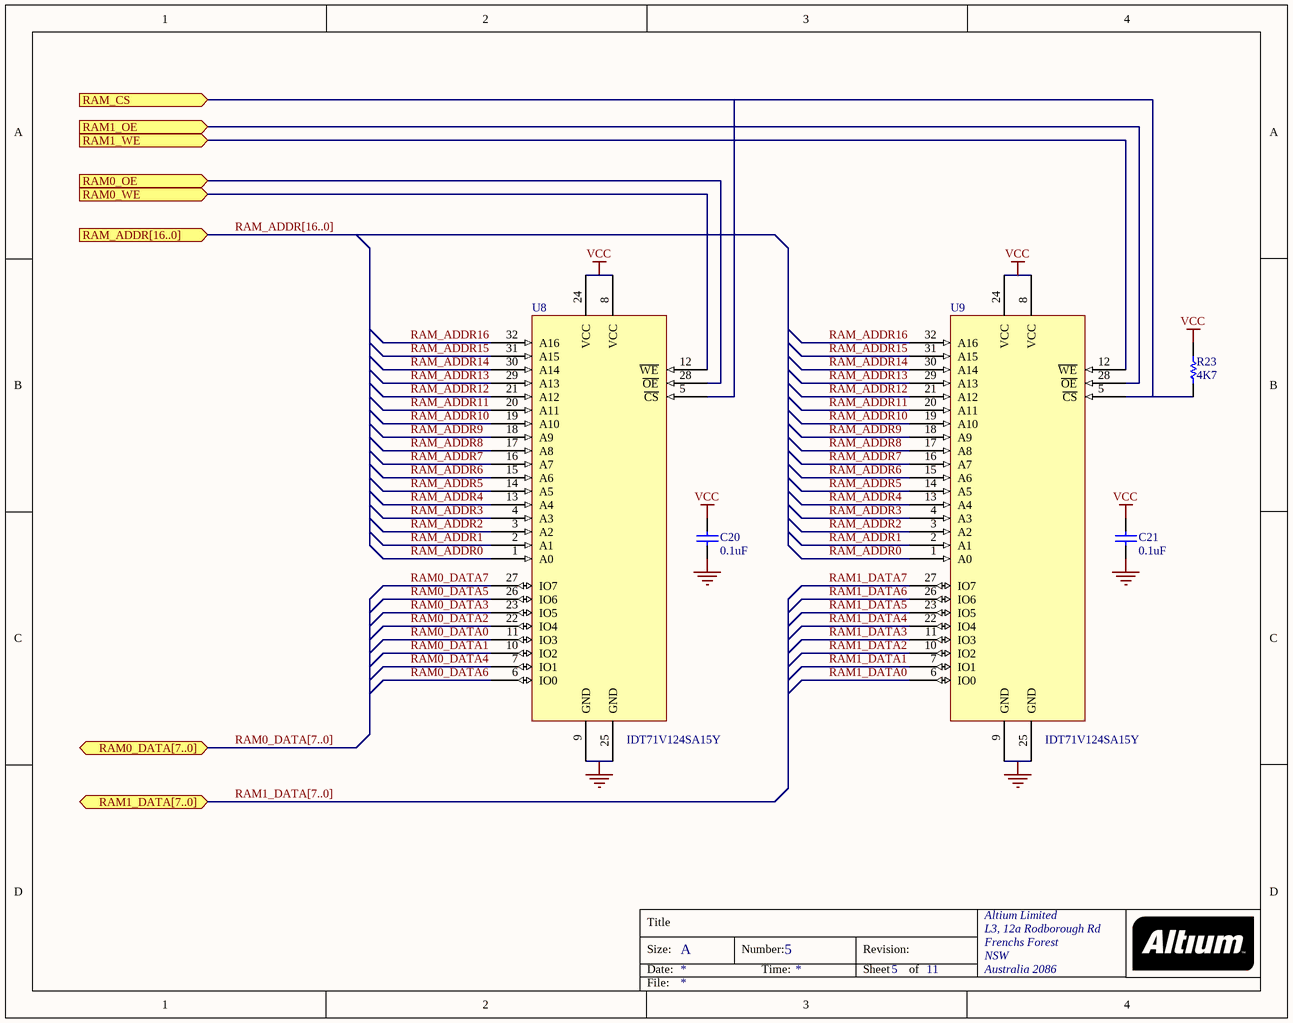
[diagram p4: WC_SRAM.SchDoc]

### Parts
C20  0.1uF  [CC2012-0805]
C21  0.1uF  [CC2012-0805]
R23  4K7  [CC2012-0805]
U8  IDT71V124SA15Y  [SO-J32]
U9  IDT71V124SA15Y  [SO-J32]

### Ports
RAM0_DATA[7..0] (bidir), RAM0_OE (in), RAM0_WE (in), RAM1_DATA[7..0] (bidir), RAM1_OE (in), RAM1_WE (in), RAM_ADDR[16..0] (in), RAM_CS (in)

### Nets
GND: C20.2 C21.2 U8.9(GND) U8.25(GND) U9.9(GND) U9.25(GND)
VCC: C20.1 C21.1 R23.1 U8.8(VCC) U8.24(VCC) U9.8(VCC) U9.24(VCC)
RAM0_DATA0: U8.11(IO3)
RAM0_DATA1: U8.10(IO2)
RAM0_DATA2: U8.22(IO4)
RAM0_DATA3: U8.23(IO5)
RAM0_DATA4: U8.7(IO1)
RAM0_DATA5: U8.26(IO6)
RAM0_DATA6: U8.6(IO0)
RAM0_DATA7: U8.27(IO7)
RAM0_OE: U8.28(~{OE}) ; port RAM0_OE
RAM0_WE: U8.12(~{WE}) ; port RAM0_WE
RAM1_DATA0: U9.6(IO0)
RAM1_DATA1: U9.7(IO1)
RAM1_DATA2: U9.10(IO2)
RAM1_DATA3: U9.11(IO3)
RAM1_DATA4: U9.22(IO4)
RAM1_DATA5: U9.23(IO5)
RAM1_DATA6: U9.26(IO6)
RAM1_DATA7: U9.27(IO7)
RAM1_OE: U9.28(~{OE}) ; port RAM1_OE
RAM1_WE: U9.12(~{WE}) ; port RAM1_WE
RAM_ADDR0: U8.1(A0) U9.1(A0)
RAM_ADDR1: U8.2(A1) U9.2(A1)
RAM_ADDR2: U8.3(A2) U9.3(A2)
RAM_ADDR3: U8.4(A3) U9.4(A3)
RAM_ADDR4: U8.13(A4) U9.13(A4)
RAM_ADDR5: U8.14(A5) U9.14(A5)
RAM_ADDR6: U8.15(A6) U9.15(A6)
RAM_ADDR7: U8.16(A7) U9.16(A7)
RAM_ADDR8: U8.17(A8) U9.17(A8)
RAM_ADDR9: U8.18(A9) U9.18(A9)
RAM_ADDR10: U8.19(A10) U9.19(A10)
RAM_ADDR11: U8.20(A11) U9.20(A11)
RAM_ADDR12: U8.21(A12) U9.21(A12)
RAM_ADDR13: U8.29(A13) U9.29(A13)
RAM_ADDR14: U8.30(A14) U9.30(A14)
RAM_ADDR15: U8.31(A15) U9.31(A15)
RAM_ADDR16: U8.32(A16) U9.32(A16)
RAM_CS: R23.2 U8.5(~{CS}) U9.5(~{CS}) ; port RAM_CS

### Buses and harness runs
bus RAM0_DATA[7..0] = port RAM0_DATA[7..0]
bus RAM1_DATA[7..0] = port RAM1_DATA[7..0]
bus RAM_ADDR[16..0] = port RAM_ADDR[16..0]

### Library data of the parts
C20 C21 = CAP: Capacitor
R23 = RES: Resistor
U8 U9 = IDT71V124SA15Y: 128K x 8 bit Fast Static RAM

## Sheet WC_VGA.SchDoc
size A; Organization: Altium Limited; Address1: L3, 12a Rodborough Rd; Address2: Frenchs Forest; Address3: NSW; Address4: Australia 2086; DocumentNumber: 6; SheetNumber: 6; SheetTotal: 11
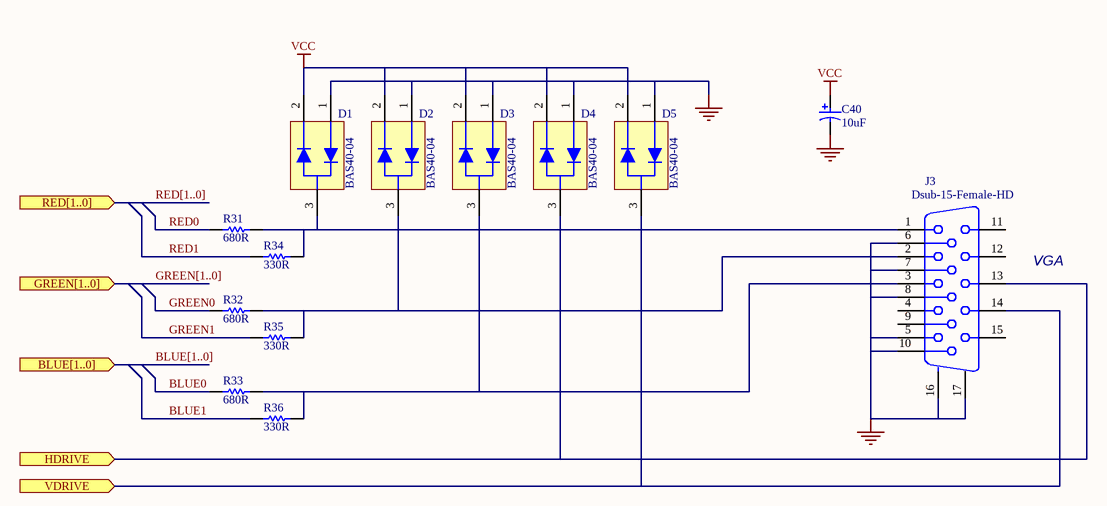
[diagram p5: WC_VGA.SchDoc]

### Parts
C40  10uF  [MCCT-B]
D1  BAS40-04  [SO-G3]
D2  BAS40-04  [SO-G3]
D3  BAS40-04  [SO-G3]
D4  BAS40-04  [SO-G3]
D5  BAS40-04  [SO-G3]
J3  Dsub-15-Female-HD  [DB15-VGA-Female]
R31  680R  [CC2012-0805]
R32  680R  [CC2012-0805]
R33  680R  [CC2012-0805]
R34  330R  [CC2012-0805]
R35  330R  [CC2012-0805]
R36  330R  [CC2012-0805]

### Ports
BLUE[1..0] (in), GREEN[1..0] (in), HDRIVE (in), RED[1..0] (in), VDRIVE (in)

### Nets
GND: C40.2 D1.1 D2.1 D3.1 D4.1 D5.1 J3.5 J3.6 J3.7 J3.8 J3.10 J3.16(MH1) J3.17(MH2)
VCC: C40.1 D1.2 D2.2 D3.2 D4.2 D5.2
BLUE0: R33.1
BLUE1: R36.1
GREEN0: R32.1
GREEN1: R35.1
RED0: R31.1
RED1: R34.1
VGA_HSYN: D4.3 J3.13 ; port HDRIVE
VGA_VSYN: D5.3 J3.14 ; port VDRIVE
NetD1_3: D1.3 J3.1 R31.2 R34.2
NetD2_3: D2.3 J3.2 R32.2 R35.2
NetD3_3: D3.3 J3.3 R33.2 R36.2

Not connected (* = marked no-connect by the designer): J3 4 9 11 12 15

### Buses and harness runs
bus BLUE[1..0] = port BLUE[1..0]
bus GREEN[1..0] = port GREEN[1..0]
bus RED[1..0] = port RED[1..0]

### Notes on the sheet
- VGA

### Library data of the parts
C40 = CAP_POLAR: Polar Capacitor
D1-D5 = BAS40-04: Shottky Diode Pair
J3 = Dsub-15-Female-HD: Dsub-15 High density VGA Female connetor; Manufacturer: Generic Components; Package Information: Latest Revision: E; Class I: Connector; Positions: 30; Gender: Receptacle Header
R31-R36 = RES: Resistor

## Sheet WC_RS232.SchDoc
size A; Organization: Altium Limited; Address1: L3, 12a Rodborough Rd; Address2: Frenchs Forest; Address3: NSW; Address4: Australia 2086; DocumentNumber: 4; SheetNumber: 4; SheetTotal: 11
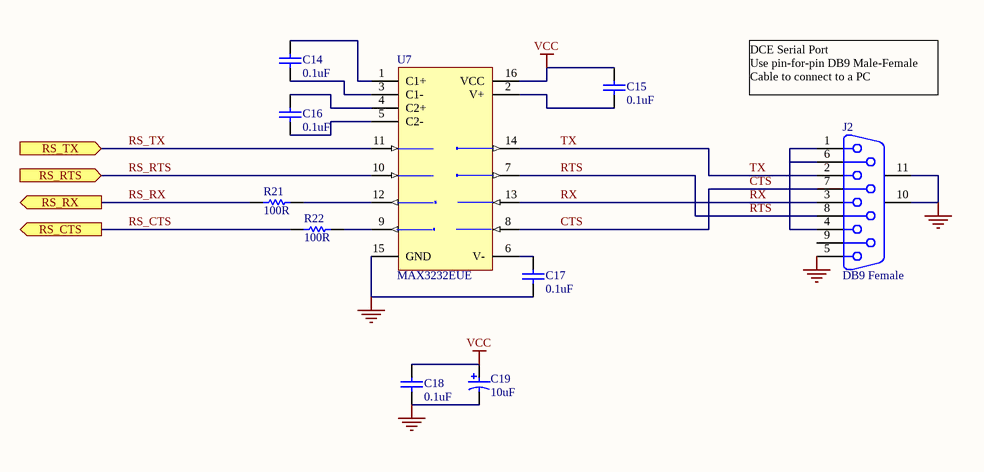
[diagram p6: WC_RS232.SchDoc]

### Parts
C14  0.1uF  [CC2012-0805]
C15  0.1uF  [CC2012-0805]
C16  0.1uF  [CC2012-0805]
C17  0.1uF  [CC2012-0805]
C18  0.1uF  [CC2012-0805]
C19  10uF  [MCCT-B]
J2  DB9 Female  [DSUB1.385-2H9]
R21  100R  [CC2012-0805]
R22  100R  [CC2012-0805]
U7  MAX3232EUE  [SO-G16]

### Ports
RS_CTS (out), RS_RTS (in), RS_RX (out), RS_TX (in)

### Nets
GND: C17.2 C18.2 C19.2 J2.5 J2.10(MH1) J2.11(MH2) U7.15(GND)
VCC: C15.1 C18.1 C19.1 U7.16(VCC)
CTS: J2.7 U7.8(R2IN)
RS_CTS: R22.1 ; port RS_CTS
RS_RTS: U7.10(T2IN) ; port RS_RTS
RS_RX: R21.1 ; port RS_RX
RS_TX: U7.11(T1IN) ; port RS_TX
RTS: J2.8 U7.7(T2OUT)
RX: J2.3 U7.13(R1IN)
TX: J2.2 U7.14(T1OUT)
NetC14_1: C14.1 U7.1(C1+)
NetC14_2: C14.2 U7.3(C1-)
NetC15_2: C15.2 U7.2(V+)
NetC16_1: C16.1 U7.4(C2+)
NetC16_2: C16.2 U7.5(C2-)
NetC17_1: C17.1 U7.6(V-)
NetJ2_1: J2.1 J2.4 J2.6
NetR21_2: R21.2 U7.12(R1OUT)
NetR22_2: R22.2 U7.9(R2OUT)

Not connected (* = marked no-connect by the designer): J2 9

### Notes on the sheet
- DCE Serial Port
  Use pin-for-pin DB9 Male-Female
  Cable to connect to a PC

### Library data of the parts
C14-C18 = CAP: Capacitor
C19 = CAP_POLAR: Polar Capacitor
J2 = D Connector 9: Receptacle Assembly, 9 Position, Right Angle; Manufacturer: Generic Components; Package Information: Latest Revision: O; Positions: 9
R21 R22 = RES: Resistor
U7 = MAX3232EUE: 3.0V TO 5.5V, Low-Power, up to 1Mbps, True RS-232 Transceiver Using Four 0.1µF External Capacitor; Manufacturer: Maxim,ST; Package Information: Latest Revision: 21-0066 C; Class I: Communication

## Sheet WC_KB.SchDoc
size A; Organization: Altium Limited; Address1: L3, 12a Rodborough Rd; Address2: Frenchs Forest; Address3: NSW; Address4: Australia 2086; DocumentNumber: 7; SheetNumber: 7; SheetTotal: 11
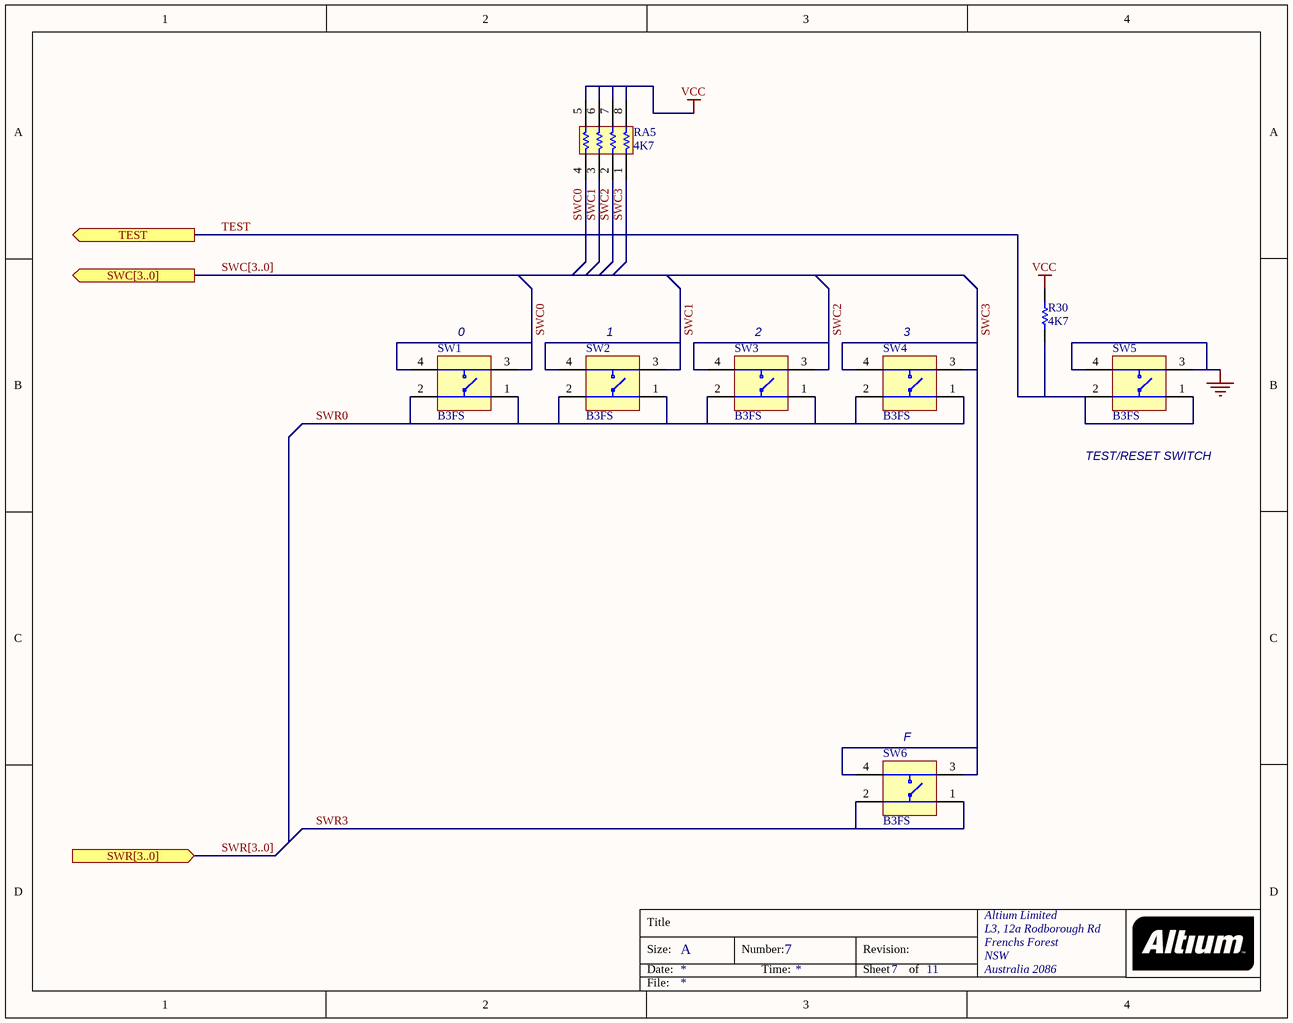
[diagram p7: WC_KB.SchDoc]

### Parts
R30  4K7  [CC2012-0805]
RA5  4K7  [MNR34]
SW1  B3FS  [B3FS_SWITCH]
SW2  B3FS  [B3FS_SWITCH]
SW3  B3FS  [B3FS_SWITCH]
SW4  B3FS  [B3FS_SWITCH]
SW5  B3FS  [B3FS_SWITCH]
SW6  B3FS  [B3FS_SWITCH]

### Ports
SWC[3..0] (out), SWR[3..0] (in), TEST (out)

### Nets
GND: SW5.3 SW5.4
VCC: R30.1 RA5.5 RA5.6 RA5.7 RA5.8
SWC0: RA5.4 SW1.3 SW1.4  [project net KP_COL0]
SWC1: RA5.3 SW2.3 SW2.4  [project net KP_COL1]
SWC2: RA5.2 SW3.3 SW3.4  [project net KP_COL2]
SWC3: RA5.1 SW4.3 SW4.4 SW6.3 SW6.4  [project net KP_COL3]
SWR0: SW1.1 SW1.2 SW2.1 SW2.2 SW3.1 SW3.2 SW4.1 SW4.2  [project net KP_ROW0]
SWR3: SW6.1 SW6.2  [project net KP_ROW3]
TEST: R30.2 SW5.1 SW5.2 ; port TEST

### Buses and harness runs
bus SWC[3..0] = port SWC[3..0]
bus SWR[3..0] = port SWR[3..0]

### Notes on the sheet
- (near SW1) 0
- (near SW2) 1
- (near SW3) 2
- (near SW4) 3
- TEST/RESET SWITCH
- (near SW6) F

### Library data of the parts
R30 = RES: Resistor
RA5 = MNR34: 3216x4 Resistor Array
SW1-SW6 = B3FS: SPNA SMD Keyboard Switch

## Sheet WC_PWR.SchDoc
size A; Organization: Altium Limited; Address1: L3, 12a Rodborough Rd; Address2: Frenchs Forest; Address3: NSW; Address4: Australia 2086; DocumentNumber: 3; SheetNumber: 3; SheetTotal: 11
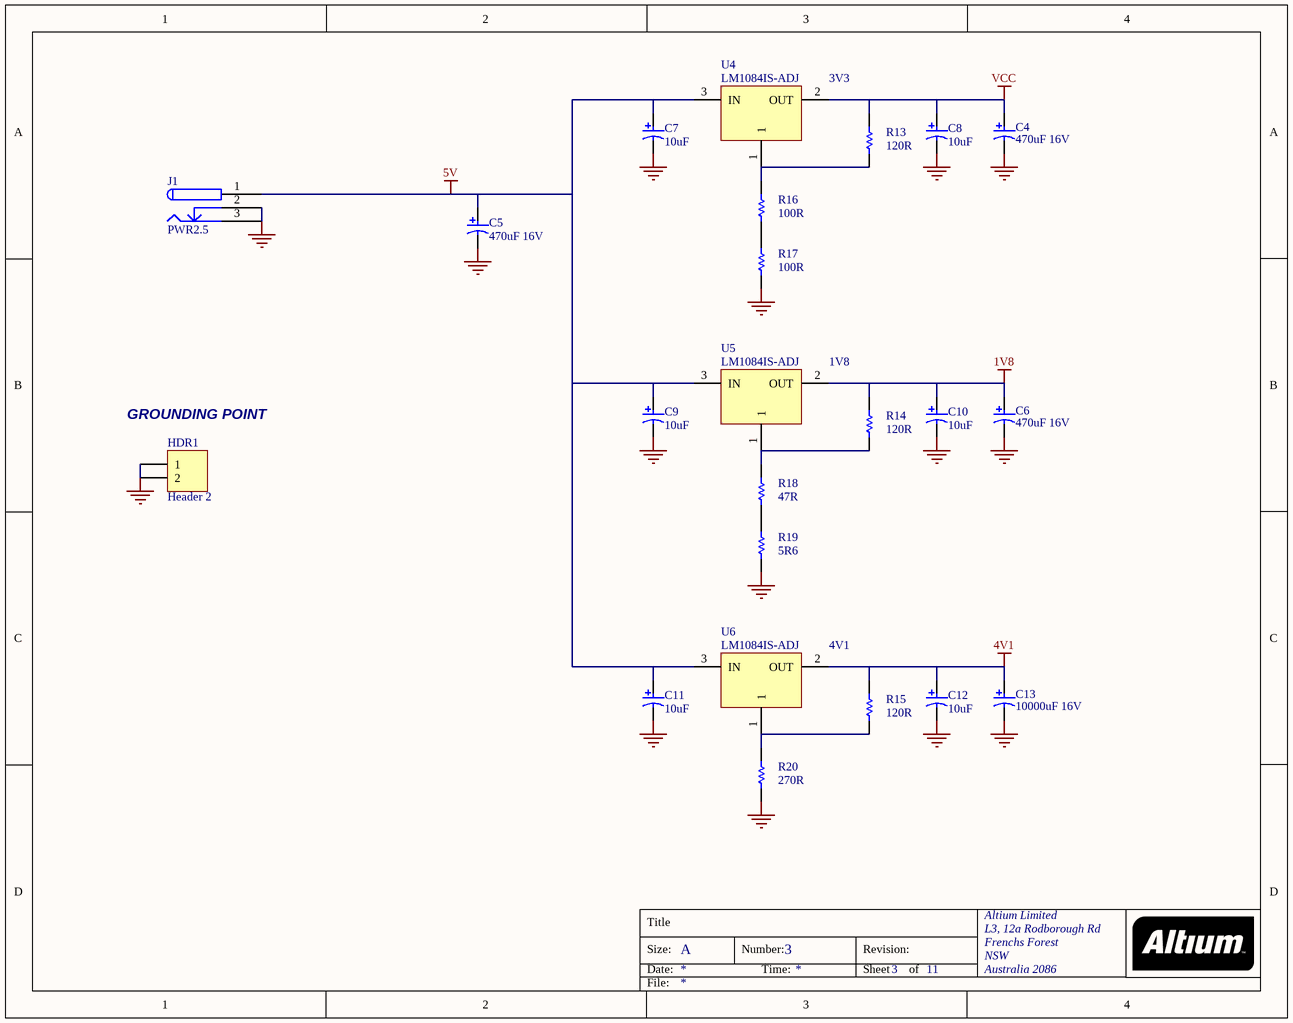
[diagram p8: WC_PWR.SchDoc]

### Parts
C4  470uF 16V  [RB8/3.5]
C5  470uF 16V  [RB8/3.5]
C6  470uF 16V  [RB8/3.5]
C7  10uF  [MCCT-B]
C8  10uF  [MCCT-B]
C9  10uF  [MCCT-B]
C10  10uF  [MCCT-B]
C11  10uF  [MCCT-B]
C12  10uF  [MCCT-B]
C13  10000uF 16V  [RB18/7.5]
HDR1  Header 2  [HDR1X2]
J1  PWR2.5  [PWR2.5]
R13  120R  [CC2012-0805]
R14  120R  [CC2012-0805]
R15  120R  [CC2012-0805]
R16  100R  [CC2012-0805]
R17  100R  [CC2012-0805]
R18  47R  [CC2012-0805]
R19  5R6  [CC2012-0805]
R20  270R  [CC2012-0805]
U4  LM1084IS-ADJ  [TO-263]
U5  LM1084IS-ADJ  [TO-263]
U6  LM1084IS-ADJ  [TO-263]

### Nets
1V8: C6.1 C10.1 R14.1 U5.2(OUT)
4V1: C12.1 C13.1 R15.1 U6.2(OUT)
5V: C5.1 C7.1 C9.1 C11.1 J1.1 U4.3(IN) U5.3(IN) U6.3(IN)
GND: C4.2 C5.2 C6.2 C7.2 C8.2 C9.2 C10.2 C11.2 C12.2 C13.2 HDR1.1 HDR1.2 J1.2 J1.3 R17.2 R19.2 R20.2
VCC: C4.1 C8.1 R13.1 U4.2(OUT)
NetR13_2: R13.2 R16.1 U4.1
NetR14_2: R14.2 R18.1 U5.1
NetR15_2: R15.2 R20.1 U6.1
NetR16_2: R16.2 R17.1
NetR18_2: R18.2 R19.1

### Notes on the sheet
- 3V3
- 1V8
- (near HDR1) GROUNDING POINT
- 4V1

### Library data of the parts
C4-C13 = CAP_POLAR: Polar Capacitor
HDR1 = Header 2: Header, 2-Pin; Manufacturer: Generic Components; Class I: Connector
J1 = PWR2.5: Low Voltage Power Supply Sonnector
R13-R20 = RES: Resistor
U4-U6 = LM1084IS-ADJ: 5A Low Dropout Possitive Regulators

## Sheet WC_Boot.SchDoc
size B; Organization: Altium Limited; Address1: L3, 12a Rodborough Rd; Address2: Frenchs Forest; Address3: NSW; Address4: Australia 2086; DocumentNumber: 8; SheetNumber: 8; SheetTotal: 11
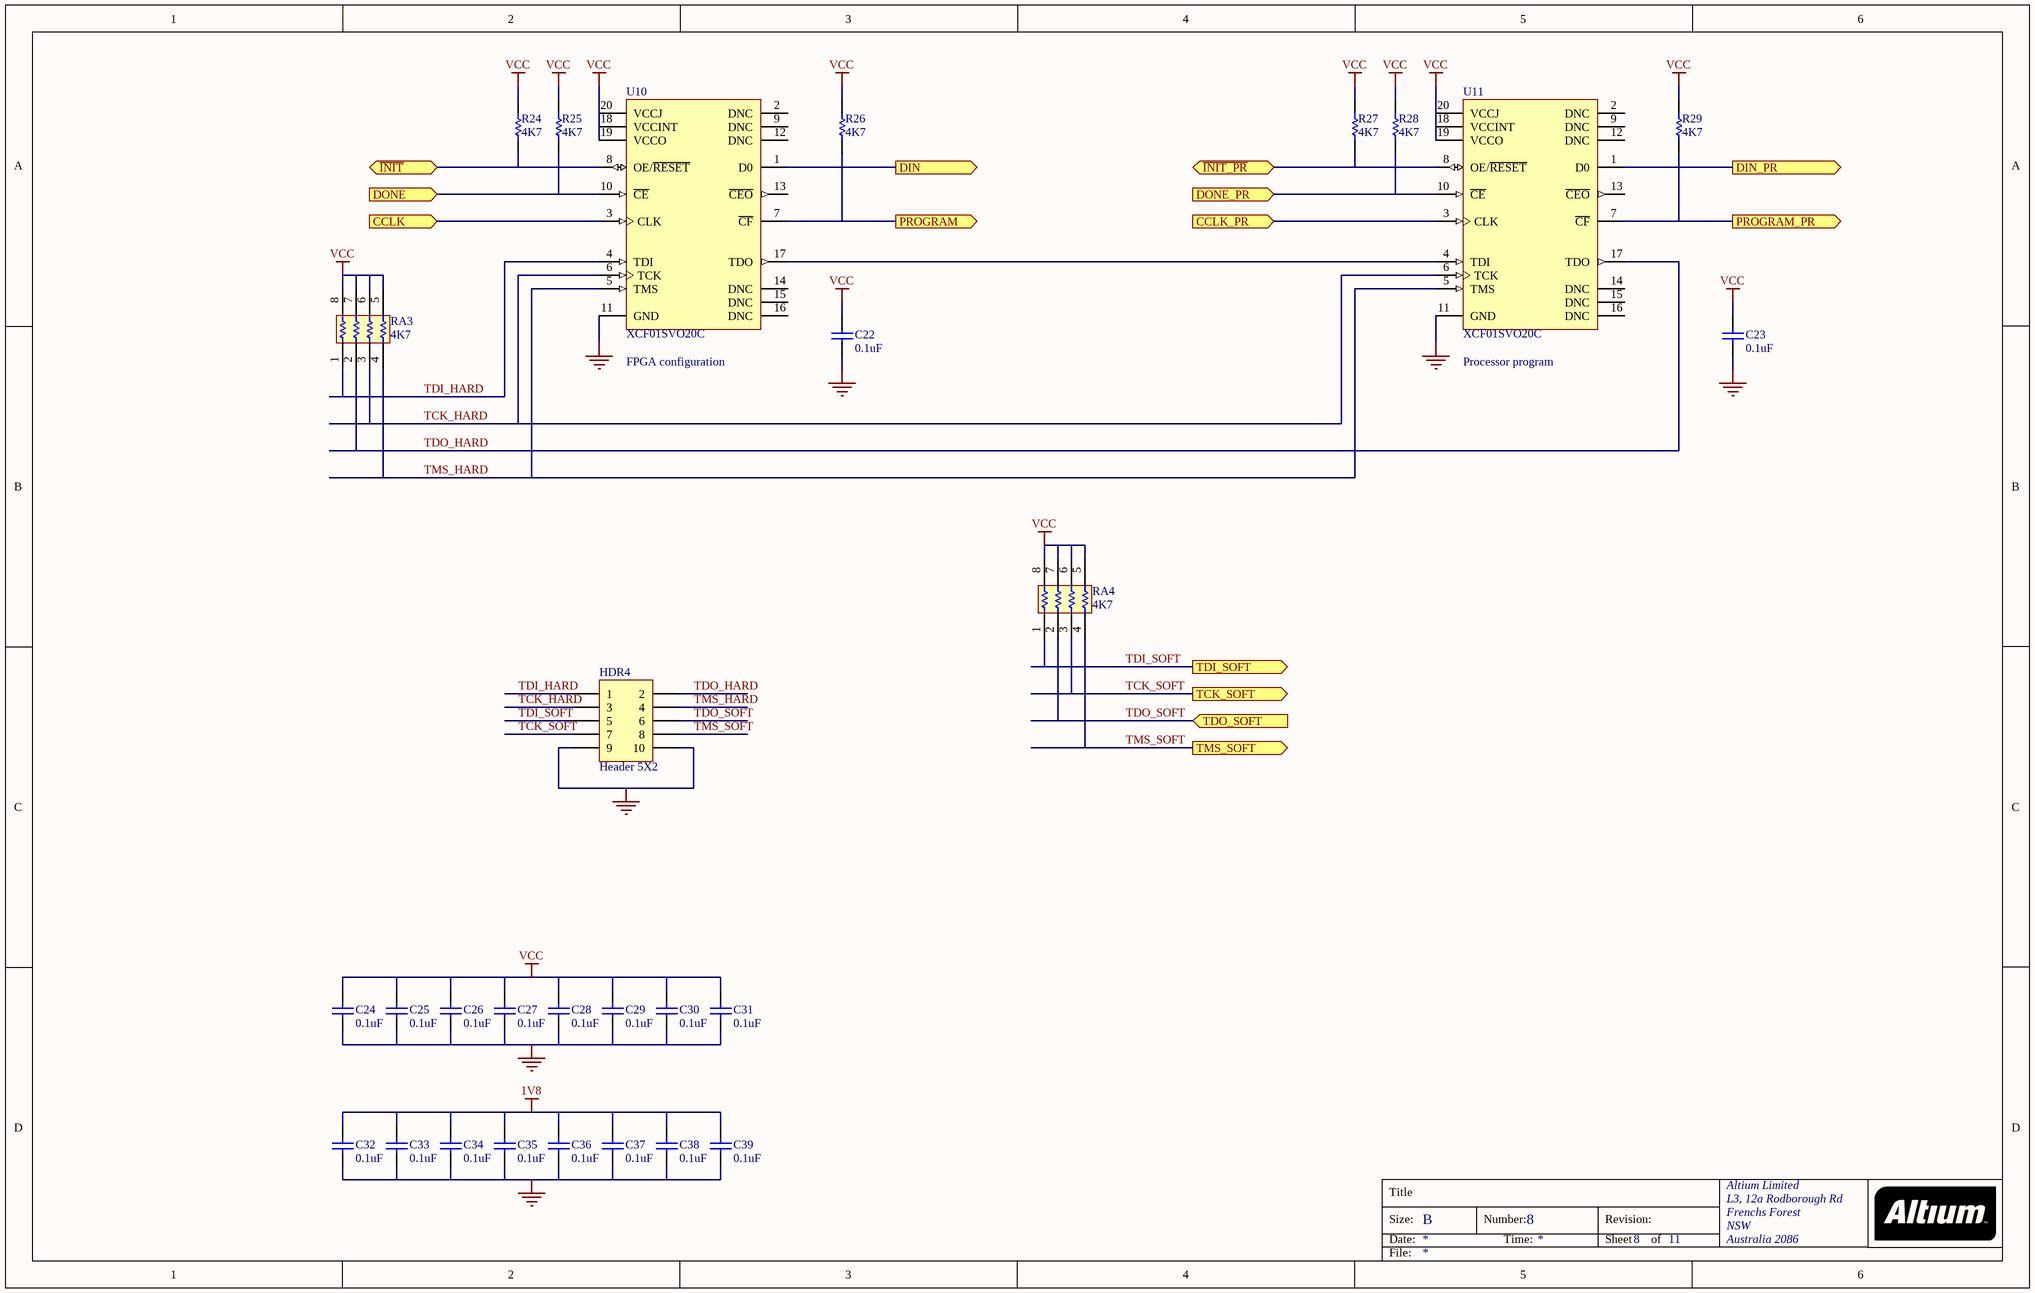
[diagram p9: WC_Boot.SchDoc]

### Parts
C22  0.1uF  [CC2012-0805]
C23  0.1uF  [CC2012-0805]
C24  0.1uF  [CC2012-0805]
C25  0.1uF  [CC2012-0805]
C26  0.1uF  [CC2012-0805]
C27  0.1uF  [CC2012-0805]
C28  0.1uF  [CC2012-0805]
C29  0.1uF  [CC2012-0805]
C30  0.1uF  [CC2012-0805]
C31  0.1uF  [CC2012-0805]
C32  0.1uF  [CC2012-0805]
C33  0.1uF  [CC2012-0805]
C34  0.1uF  [CC2012-0805]
C35  0.1uF  [CC2012-0805]
C36  0.1uF  [CC2012-0805]
C37  0.1uF  [CC2012-0805]
C38  0.1uF  [CC2012-0805]
C39  0.1uF  [CC2012-0805]
HDR4  Header 5X2  [HDR2X5]
R24  4K7  [CC2012-0805]
R25  4K7  [CC2012-0805]
R26  4K7  [CC2012-0805]
R27  4K7  [CC2012-0805]
R28  4K7  [CC2012-0805]
R29  4K7  [CC2012-0805]
RA3  4K7  [MNR34]
RA4  4K7  [MNR34]
U10  XCF01SVO20C  usage: FPGA configuration  [VO20]
U11  XCF01SVO20C  usage: Processor program  [VO20]

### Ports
CCLK (in), CCLK_PR (in), DIN (out), DIN_PR (out), DONE (in), DONE_PR (in), PROGRAM (out), PROGRAM_PR (out), TCK_SOFT (out), TDI_SOFT (out), TDO_SOFT (in), TMS_SOFT (out), ~{INIT_PR} (bidir), ~{INIT} (bidir)

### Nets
1V8: C32.1 C33.1 C34.1 C35.1 C36.1 C37.1 C38.1 C39.1
GND: C22.1 C23.1 C24.2 C25.2 C26.2 C27.2 C28.2 C29.2 C30.2 C31.2 C32.2 C33.2 C34.2 C35.2 C36.2 C37.2 C38.2 C39.2 HDR4.9 HDR4.10 U10.11(GND) U11.11(GND)
VCC: C22.2 C23.2 C24.1 C25.1 C26.1 C27.1 C28.1 C29.1 C30.1 C31.1 R24.1 R25.1 R26.1 R27.1 R28.1 R29.1 RA3.5 RA3.6 RA3.7 RA3.8 RA4.5 RA4.6 RA4.7 RA4.8 U10.18(VCCINT) U10.19(VCCO) U10.20(VCCJ) U11.18(VCCINT) U11.19(VCCO) U11.20(VCCJ)
CCLK: U10.3(CLK) ; port CCLK
CCLK_PR: U11.3(CLK) ; port CCLK_PR
DIN: U10.1(D0) ; port DIN
DIN_PR: U11.1(D0) ; port DIN_PR
DONE: R25.2 U10.10(~{CE}) ; port DONE
DONE_PR: R28.2 U11.10(~{CE}) ; port DONE_PR
~{INIT}: R24.2 U10.8(OE/~{RESET}) ; port ~{INIT}
~{INIT_PR}: R27.2 U11.8(OE/~{RESET}) ; port ~{INIT_PR}
PROGRAM: R26.2 U10.7(~{CF}) ; port PROGRAM
PROGRAM_PR: R29.2 U11.7(~{CF}) ; port PROGRAM_PR
TCK_HARD: HDR4.3 RA3.3 U10.6(TCK) U11.6(TCK)
TCK_SOFT: HDR4.7 RA4.3 ; port TCK_SOFT  [project net JTAG_NEXUS_TCK]
TDI_HARD: HDR4.1 RA3.1 U10.4(TDI)
TDI_SOFT: HDR4.5 RA4.1 ; port TDI_SOFT  [project net JTAG_NEXUS_TDI]
TDO_HARD: HDR4.2 RA3.2 U11.17(TDO)
TDO_SOFT: HDR4.6 RA4.2 ; port TDO_SOFT  [project net JTAG_NEXUS_TDO]
TMS_HARD: HDR4.4 RA3.4 U10.5(TMS) U11.5(TMS)
TMS_SOFT: HDR4.8 RA4.4 ; port TMS_SOFT  [project net JTAG_NEXUS_TMS]
NetU10_17: U10.17(TDO) U11.4(TDI)

Not connected (* = marked no-connect by the designer): U10 2(DNC) 9(DNC) 12(DNC) 13(~{CEO}) 14(DNC) 15(DNC) 16(DNC); U11 2(DNC) 9(DNC) 12(DNC) 13(~{CEO}) 14(DNC) 15(DNC) 16(DNC)

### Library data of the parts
C22-C39 = CAP: Capacitor
HDR4 = Header 5X2: Header, 5-Pin, Dual row; Manufacturer: Generic Components; Class I: Connector
R24-R29 = RES: Resistor
RA3 RA4 = MNR34: 3216x4 Resistor Array
U10 U11 = XCF01SVO20C: XCF00S Series, Platform Flash In-System Programmable Configuration 3.3V PROM, 1-Megabit, Commercial Grade; Manufacturer: Xilinx; Package Information: Latest Revision: ver1.0, May-2003; Class I: Memory; Code - JEDEC: MO-153-AC

## Sheet WC_MODEM.SchDoc
size A; Organization: Altium Limited; Address1: L3, 12a Rodborough Rd; Address2: Frenchs Forest; Address3: NSW; Address4: Australia 2086; DocumentNumber: 9; SheetNumber: 9; SheetTotal: 11
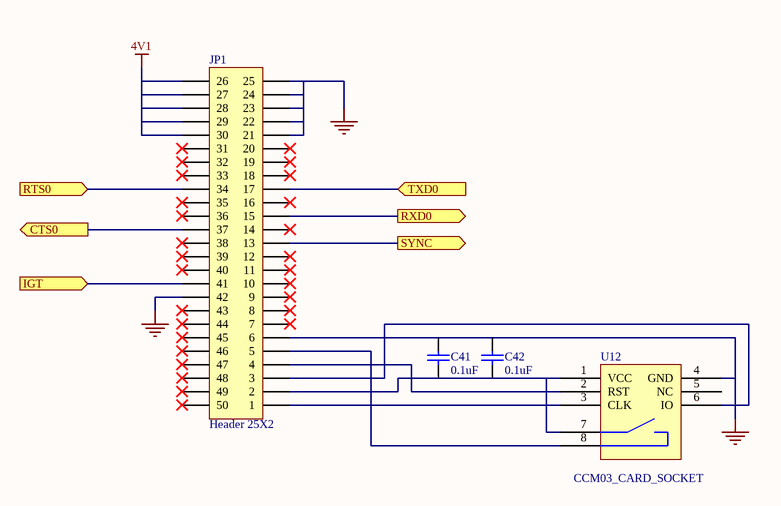
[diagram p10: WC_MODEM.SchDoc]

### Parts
C41  0.1uF  [CC2012-0805]
C42  0.1uF  [CC2012-0805]
JP1  Header 25X2  [MC45]
U12  CCM03_CARD_SOCKET  [CCM03_MKIII]

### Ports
CTS0 (out), IGT (in), RTS0 (in), RXD0 (out), SYNC (out), TXD0 (in)

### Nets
4V1: JP1.26 JP1.27 JP1.28 JP1.29 JP1.30
GND: C41.2 C42.2 JP1.6 JP1.21 JP1.22 JP1.23 JP1.24 JP1.25 JP1.42 U12.4(GND)
GSM_CTS: JP1.37 ; port CTS0
GSM_IGT: JP1.41 ; port IGT
GSM_RTS: JP1.34 ; port RTS0
GSM_RXD: JP1.15 ; port RXD0
GSM_SYNC: JP1.13 ; port SYNC
GSM_TXD: JP1.17 ; port TXD0
NetC41_1: C41.1 C42.1 JP1.2 U12.1(VCC) U12.7
NetJP1_1: JP1.1 U12.3(CLK)
NetJP1_3: JP1.3 U12.6(IO)
NetJP1_4: JP1.4 U12.2(RST)
NetJP1_5: JP1.5 U12.8

Not connected (* = marked no-connect by the designer): JP1 7* 8* 9* 10* 11* 12* 14* 16* 18* 19* 20* 31* 32* 33* 35* 36* 38* 39* 40* 43* 44* 45* 46* 47* 48* 49* 50*; U12 5(NC)

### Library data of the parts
C41 C42 = CAP: Capacitor
JP1 = Header 25X2: Header, 25-Pin, Dual row; Manufacturer: Generic Components; Class I: Connector
U12 = CCM03_CARD_SOCKET: SIM/SAM card connector with card detection switch

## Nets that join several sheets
1V8: FPGA_U1_Auto (12 pins), WC_PWR (C6.1 C10.1 R14.1 U5.2), WC_Boot (8 pins)
4V1: WC_PWR (C12.1 C13.1 R15.1 U6.2), WC_MODEM (5 pins)
5V: WC_LCD (LCD1.15 R11.1), WC_PWR (8 pins)
GND: FPGA_U1_Manual (C1.2 U2.2), FPGA_U1_Auto (26 pins), WC_SENS (R39.1), WC_LCD (8 pins), WC_SRAM (6 pins), WC_VGA (13 pins), WC_RS232 (7 pins), WC_KB (SW5.3 SW5.4), WC_PWR (17 pins), WC_Boot (22 pins), WC_MODEM (10 pins)
VCC: FPGA_U1_Manual (7 pins), FPGA_U1_Auto (17 pins), WC_SENS (R37.1 R38.1 R42.1), WC_LCD (C3.1 R6.2 R12.1 U3.20), WC_SRAM (7 pins), WC_VGA (6 pins), WC_RS232 (C15.1 C18.1 C19.1 U7.16), WC_KB (5 pins), WC_PWR (C4.1 C8.1 R13.1 U4.2), WC_Boot (30 pins)
BLUE0: FPGA_U1_Auto (U1.40), WC_VGA (R33.1)
BLUE1: FPGA_U1_Auto (U1.41), WC_VGA (R36.1)
CCLK: FPGA_U1_Auto (U1.155), WC_Boot (U10.3)
CCLK_PR: FPGA_U1_Auto (U1.198), WC_Boot (U11.3)
CLK_BRD: FPGA_U1_Manual (U2.3), FPGA_U1_Auto (U1.182)
DIN: FPGA_U1_Auto (U1.153), WC_Boot (U10.1)
DIN_PR: FPGA_U1_Auto (U1.199), WC_Boot (U11.1)
DONE: FPGA_U1_Auto (U1.104), WC_Boot (R25.2 U10.10)
DONE_PR: FPGA_U1_Auto (U1.202), WC_Boot (R28.2 U11.10)
GREEN0: FPGA_U1_Auto (U1.42), WC_VGA (R32.1)
GREEN1: FPGA_U1_Auto (U1.43), WC_VGA (R35.1)
GSM_CTS: FPGA_U1_Auto (U1.146), WC_MODEM (JP1.37)
GSM_IGT: FPGA_U1_Auto (U1.147), WC_MODEM (JP1.41)
GSM_RTS: FPGA_U1_Auto (U1.145), WC_MODEM (JP1.34)
GSM_RXD: FPGA_U1_Auto (U1.126), WC_MODEM (JP1.15)
GSM_SYNC: FPGA_U1_Auto (U1.125), WC_MODEM (JP1.13)
GSM_TXD: FPGA_U1_Auto (U1.127), WC_MODEM (JP1.17)
~{INIT}: FPGA_U1_Auto (U1.107), WC_Boot (R24.2 U10.8)
~{INIT_PR}: FPGA_U1_Auto (U1.201), WC_Boot (R27.2 U11.8)
JTAG_NEXUS_TCK: FPGA_U1_Auto (U1.164), WC_Boot (HDR4.7 RA4.3)
JTAG_NEXUS_TDI: FPGA_U1_Auto (U1.166), WC_Boot (HDR4.5 RA4.1)
JTAG_NEXUS_TDO: FPGA_U1_Auto (U1.165), WC_Boot (HDR4.6 RA4.2)
JTAG_NEXUS_TMS: FPGA_U1_Auto (U1.163), WC_Boot (HDR4.8 RA4.4)
KP_COL0: FPGA_U1_Auto (U1.111), WC_KB (RA5.4 SW1.3 SW1.4)
KP_COL1: FPGA_U1_Auto (U1.112), WC_KB (RA5.3 SW2.3 SW2.4)
KP_COL2: FPGA_U1_Auto (U1.113), WC_KB (RA5.2 SW3.3 SW3.4)
KP_COL3: FPGA_U1_Auto (U1.114), WC_KB (5 pins)
KP_ROW0: FPGA_U1_Auto (U1.109), WC_KB (8 pins)
KP_ROW3: FPGA_U1_Auto (U1.110), WC_KB (SW6.1 SW6.2)
LCD_BCKL: FPGA_U1_Auto (U1.34), WC_LCD (R9.1)
LCD_E: FPGA_U1_Auto (U1.108), WC_LCD (LCD1.6 R5.1)
LCD_EDATA: FPGA_U1_Auto (U1.55), WC_LCD (R6.1 U3.19)
PROGRAM: FPGA_U1_Auto (U1.106), WC_Boot (R26.2 U10.7)
PROGRAM_PR: FPGA_U1_Auto (U1.200), WC_Boot (R29.2 U11.7)
RAM0_DATA0: FPGA_U1_Auto (U1.99), WC_LCD (U3.11), WC_SRAM (U8.11)
RAM0_DATA1: FPGA_U1_Auto (U1.100), WC_LCD (U3.12), WC_SRAM (U8.10)
RAM0_DATA2: FPGA_U1_Auto (U1.101), WC_LCD (U3.13), WC_SRAM (U8.22)
RAM0_DATA3: FPGA_U1_Auto (U1.102), WC_LCD (U3.14), WC_SRAM (U8.23)
RAM0_DATA4: FPGA_U1_Auto (U1.46), WC_LCD (U3.15), WC_SRAM (U8.7)
RAM0_DATA5: FPGA_U1_Auto (U1.47), WC_LCD (U3.16), WC_SRAM (U8.26)
RAM0_DATA6: FPGA_U1_Auto (U1.48), WC_LCD (U3.17), WC_SRAM (U8.6)
RAM0_DATA7: FPGA_U1_Auto (U1.49), WC_LCD (U3.18), WC_SRAM (U8.27)
RAM0_OE: FPGA_U1_Auto (U1.56), WC_SRAM (U8.28)
RAM0_WE: FPGA_U1_Auto (U1.98), WC_SRAM (U8.12)
RAM1_DATA0: FPGA_U1_Auto (U1.71), WC_SRAM (U9.6)
RAM1_DATA1: FPGA_U1_Auto (U1.74), WC_SRAM (U9.7)
RAM1_DATA2: FPGA_U1_Auto (U1.75), WC_SRAM (U9.10)
RAM1_DATA3: FPGA_U1_Auto (U1.82), WC_SRAM (U9.11)
RAM1_DATA4: FPGA_U1_Auto (U1.83), WC_SRAM (U9.22)
RAM1_DATA5: FPGA_U1_Auto (U1.81), WC_SRAM (U9.23)
RAM1_DATA6: FPGA_U1_Auto (U1.73), WC_SRAM (U9.26)
RAM1_DATA7: FPGA_U1_Auto (U1.70), WC_SRAM (U9.27)
RAM1_OE: FPGA_U1_Auto (U1.68), WC_SRAM (U9.28)
RAM1_WE: FPGA_U1_Auto (U1.84), WC_SRAM (U9.12)
RAM_ADDR0: FPGA_U1_Auto (U1.58), WC_LCD (LCD1.4), WC_SRAM (U8.1 U9.1)
RAM_ADDR1: FPGA_U1_Auto (U1.60), WC_LCD (LCD1.5 U3.1), WC_SRAM (U8.2 U9.2)
RAM_ADDR2: FPGA_U1_Auto (U1.62), WC_SRAM (U8.3 U9.3)
RAM_ADDR3: FPGA_U1_Auto (U1.64), WC_SRAM (U8.4 U9.4)
RAM_ADDR4: FPGA_U1_Auto (U1.87), WC_SRAM (U8.13 U9.13)
RAM_ADDR5: FPGA_U1_Auto (U1.89), WC_SRAM (U8.14 U9.14)
RAM_ADDR6: FPGA_U1_Auto (U1.94), WC_SRAM (U8.15 U9.15)
RAM_ADDR7: FPGA_U1_Auto (U1.96), WC_SRAM (U8.16 U9.16)
RAM_ADDR8: FPGA_U1_Auto (U1.97), WC_SRAM (U8.17 U9.17)
RAM_ADDR9: FPGA_U1_Auto (U1.95), WC_SRAM (U8.18 U9.18)
RAM_ADDR10: FPGA_U1_Auto (U1.93), WC_SRAM (U8.19 U9.19)
RAM_ADDR11: FPGA_U1_Auto (U1.88), WC_SRAM (U8.20 U9.20)
RAM_ADDR12: FPGA_U1_Auto (U1.86), WC_SRAM (U8.21 U9.21)
RAM_ADDR13: FPGA_U1_Auto (U1.63), WC_SRAM (U8.29 U9.29)
RAM_ADDR14: FPGA_U1_Auto (U1.61), WC_SRAM (U8.30 U9.30)
RAM_ADDR15: FPGA_U1_Auto (U1.59), WC_SRAM (U8.31 U9.31)
RAM_ADDR16: FPGA_U1_Auto (U1.57), WC_SRAM (U8.32 U9.32)
RAM_CS: FPGA_U1_Auto (U1.69), WC_SRAM (R23.2 U8.5 U9.5)
RED0: FPGA_U1_Auto (U1.44), WC_VGA (R31.1)
RED1: FPGA_U1_Auto (U1.45), WC_VGA (R34.1)
RS_CTS: FPGA_U1_Auto (U1.121), WC_RS232 (R22.1)
RS_RTS: FPGA_U1_Auto (U1.120), WC_RS232 (U7.10)
RS_RX: FPGA_U1_Auto (U1.115), WC_RS232 (R21.1)
RS_TX: FPGA_U1_Auto (U1.116), WC_RS232 (U7.11)
SCL: FPGA_U1_Auto (U1.149), WC_SENS (R37.2 U13.5)
SDA: FPGA_U1_Auto (U1.148), WC_SENS (R38.2 U13.6)
SPEED: FPGA_U1_Auto (U1.150), WC_SENS (J4.4 R40.2)
TCK: FPGA_U1_Manual (R3.2), FPGA_U1_Auto (U1.207)
TDI: FPGA_U1_Manual (R2.2), FPGA_U1_Auto (U1.159)
TDO: FPGA_U1_Manual (R1.2), FPGA_U1_Auto (U1.157)
TEST: FPGA_U1_Auto (U1.203), WC_KB (R30.2 SW5.1 SW5.2)
TMS: FPGA_U1_Manual (R4.2), FPGA_U1_Auto (U1.2)
VGA_HSYN: FPGA_U1_Auto (U1.36), WC_VGA (D4.3 J3.13)
VGA_VSYN: FPGA_U1_Auto (U1.35), WC_VGA (D5.3 J3.14)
